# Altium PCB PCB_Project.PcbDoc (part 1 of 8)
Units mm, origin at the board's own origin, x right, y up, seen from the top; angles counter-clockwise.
Board outline 250 x 200 mm, 6 copper layers (Top Shielding/Sig, Sig 1, PWR, GND, Sig 4, Bottom Shielding/Sig), stack 1.568 mm thick; 736 components, 420 nets, 1929 pads, 2185 vias.
Unrouted connection lines stored in the file: 47.
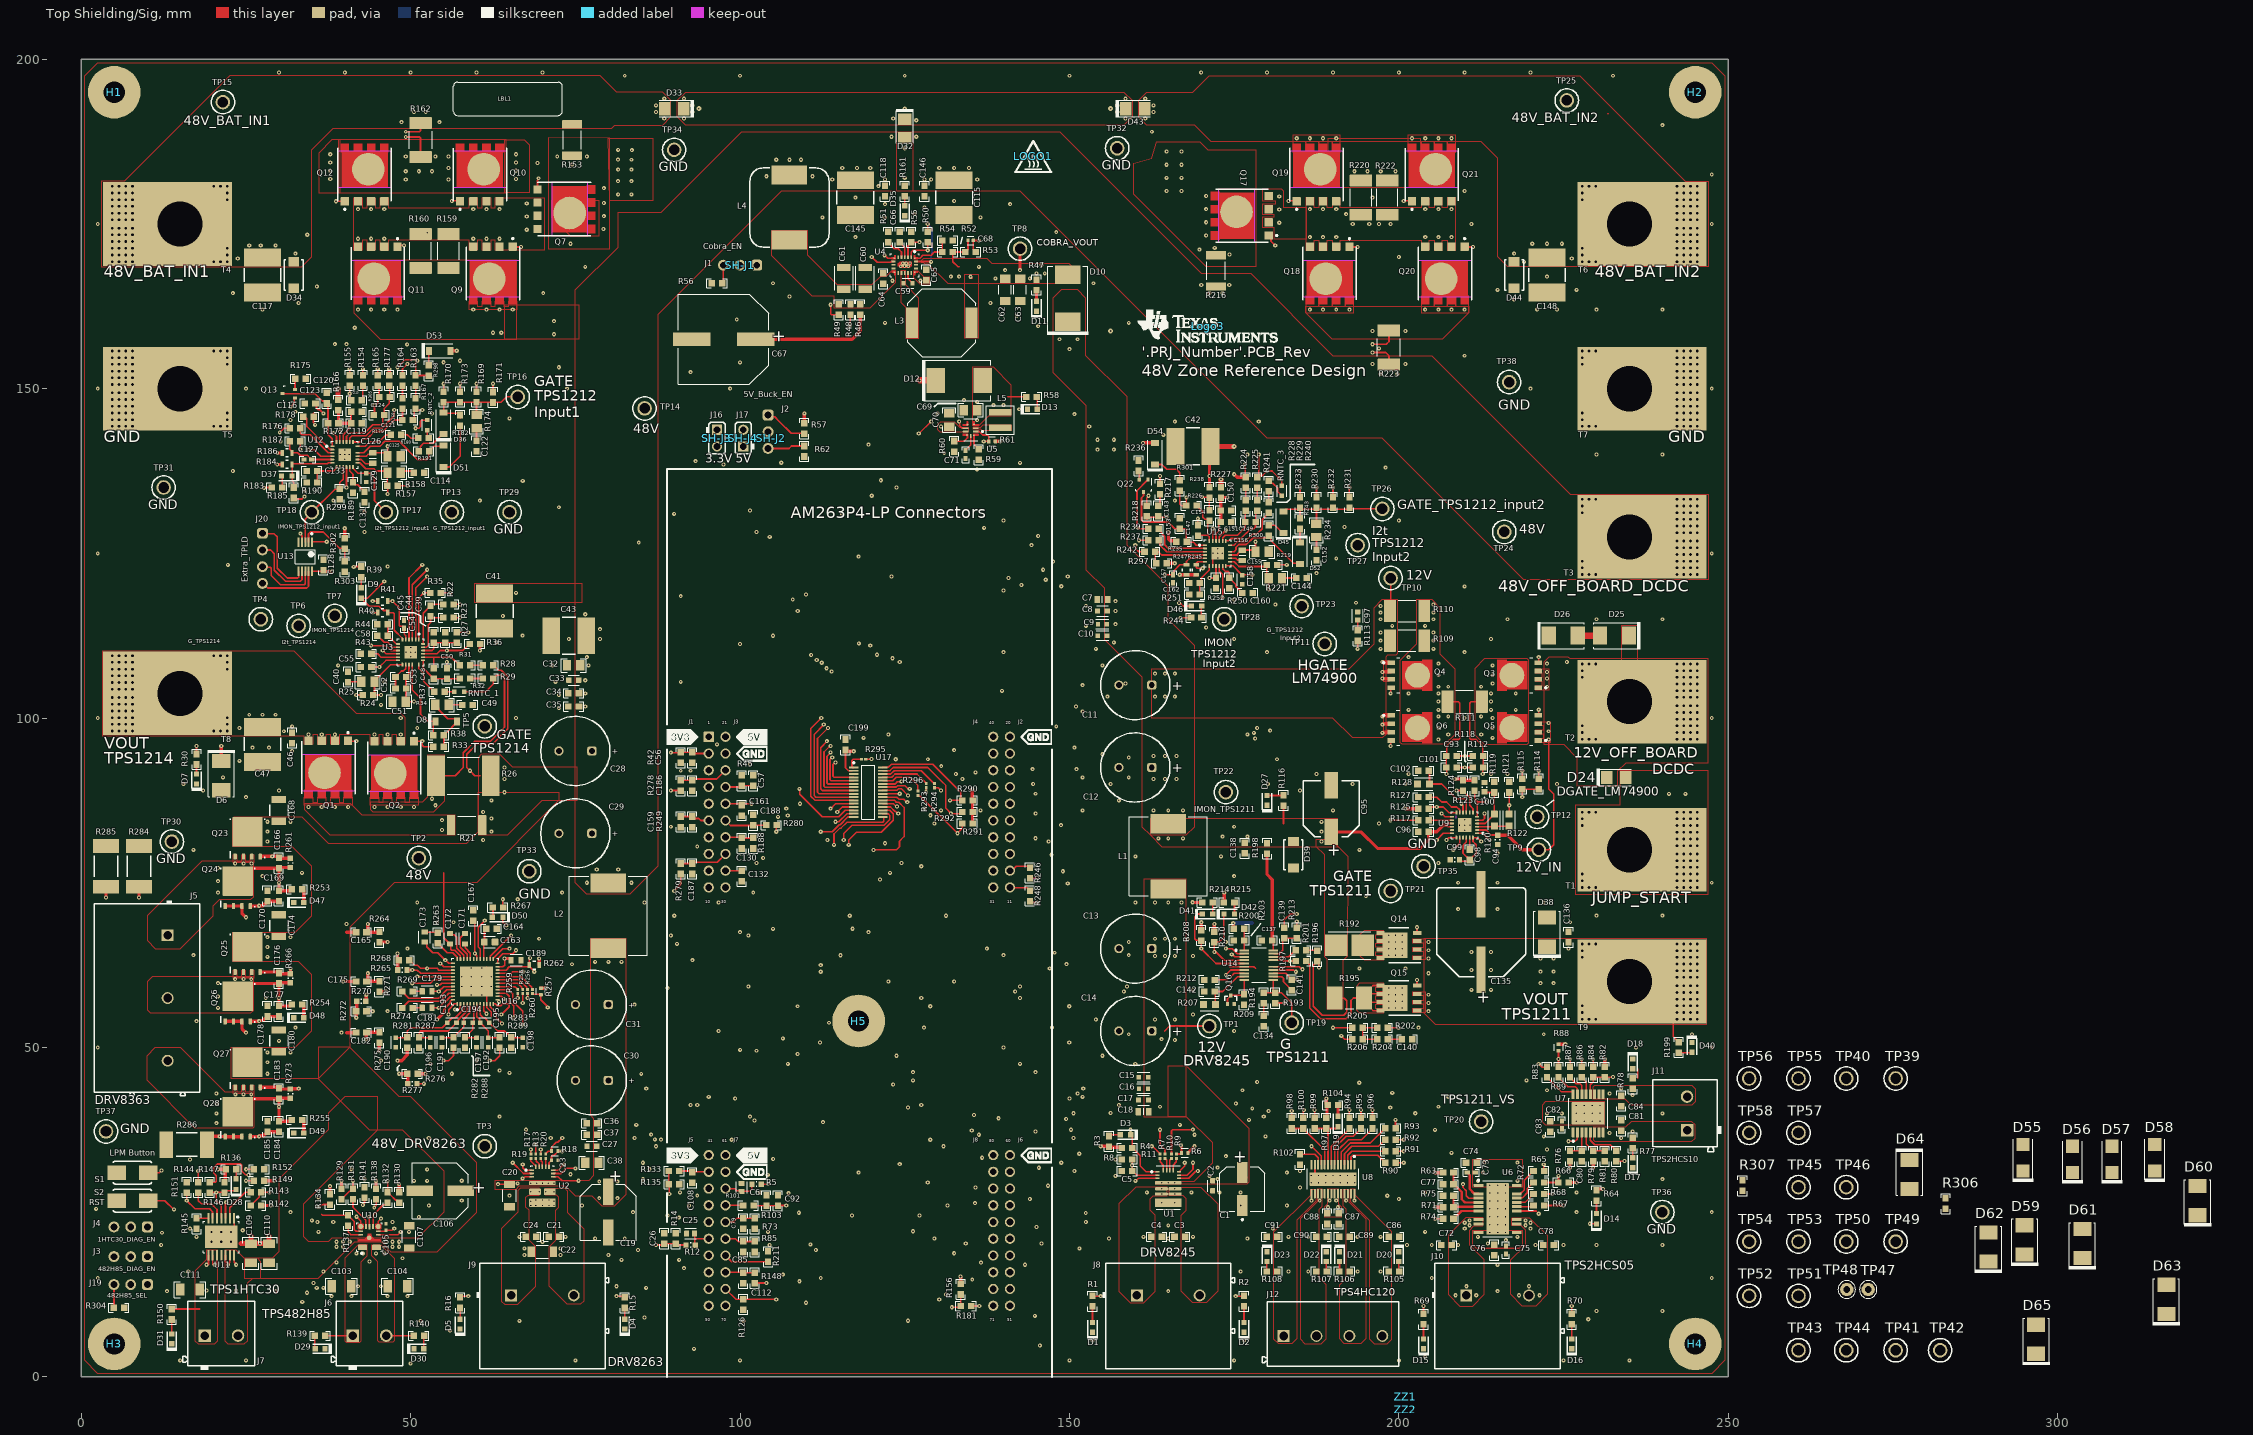
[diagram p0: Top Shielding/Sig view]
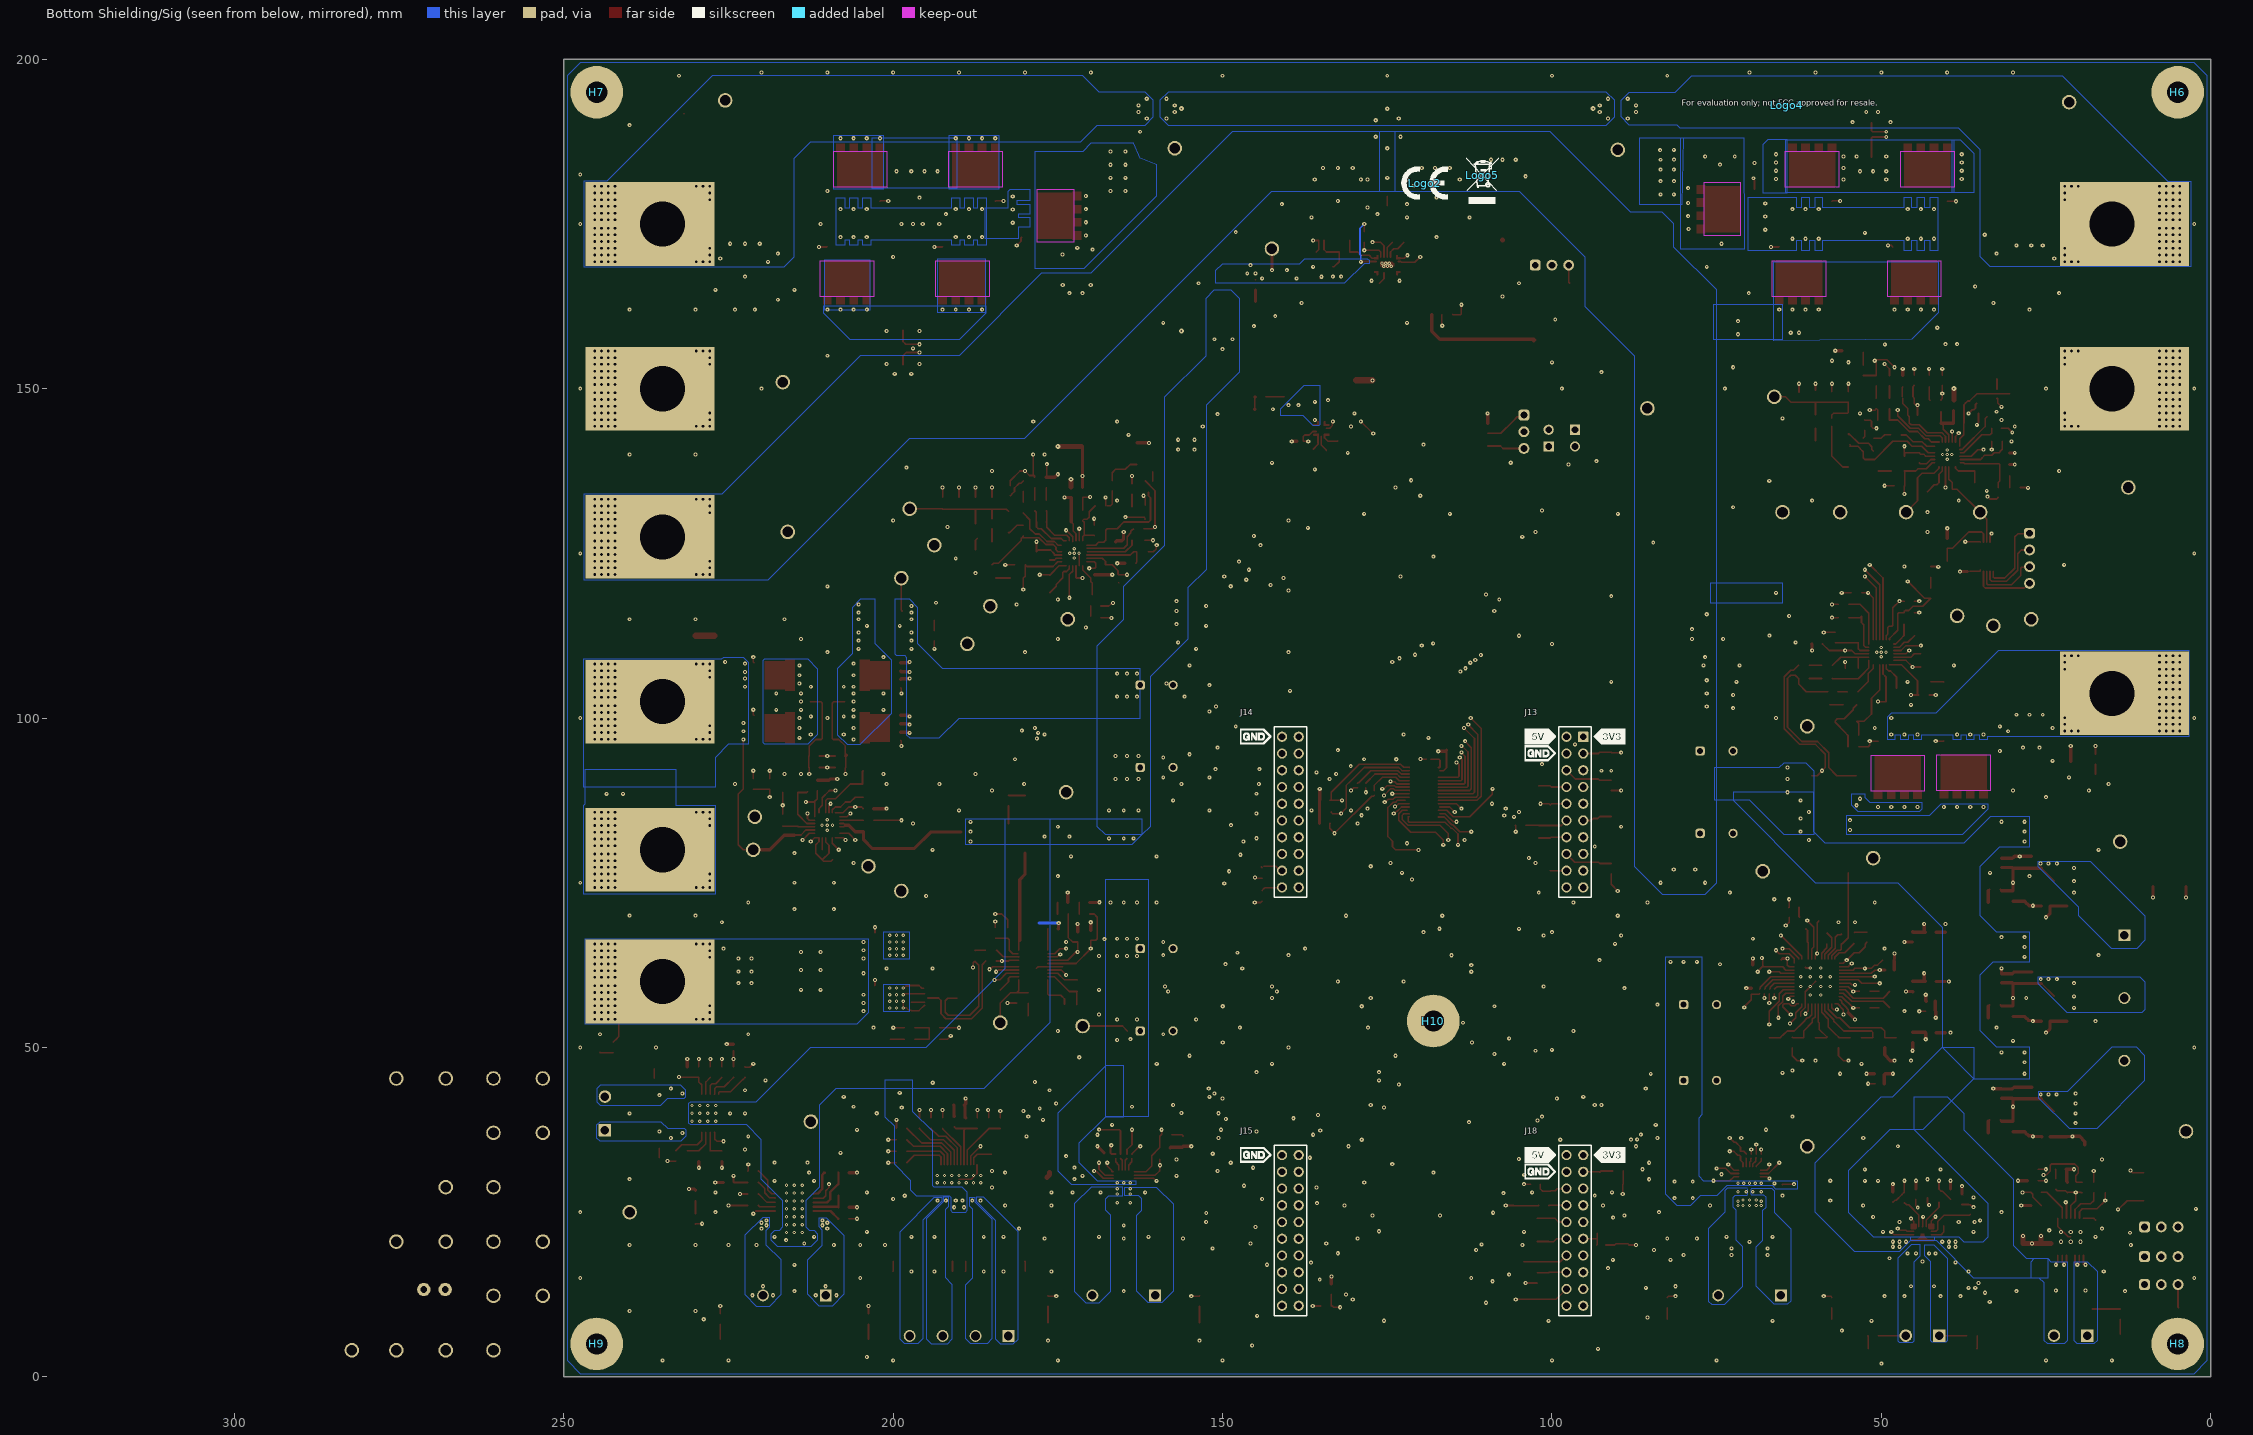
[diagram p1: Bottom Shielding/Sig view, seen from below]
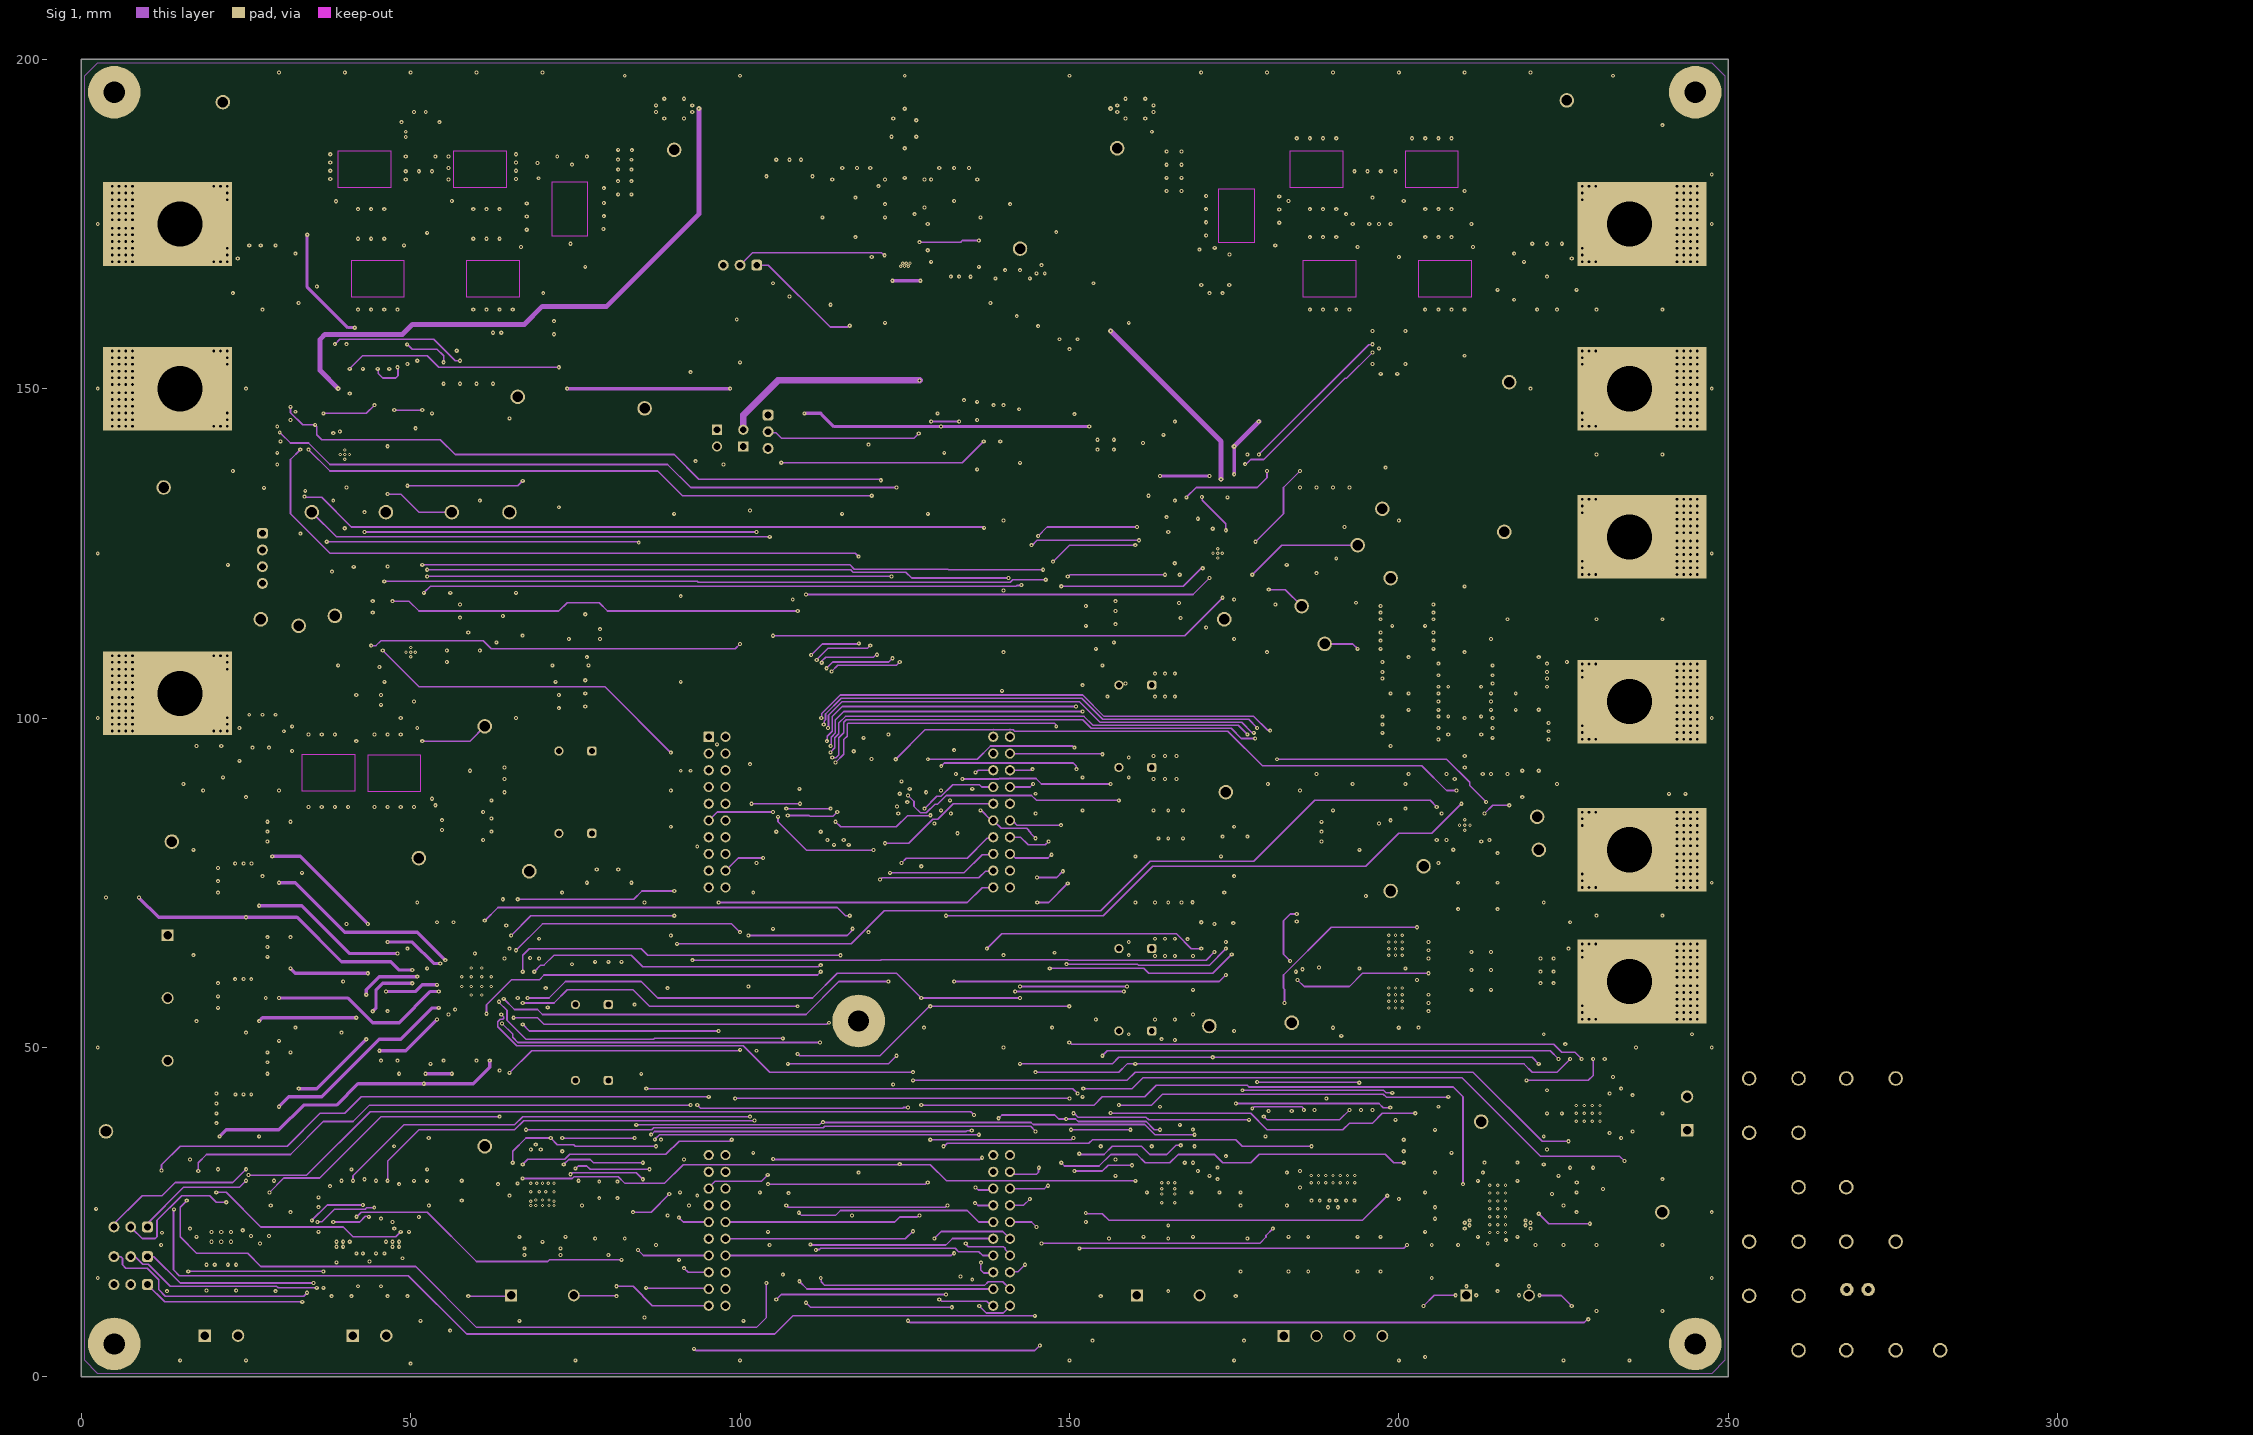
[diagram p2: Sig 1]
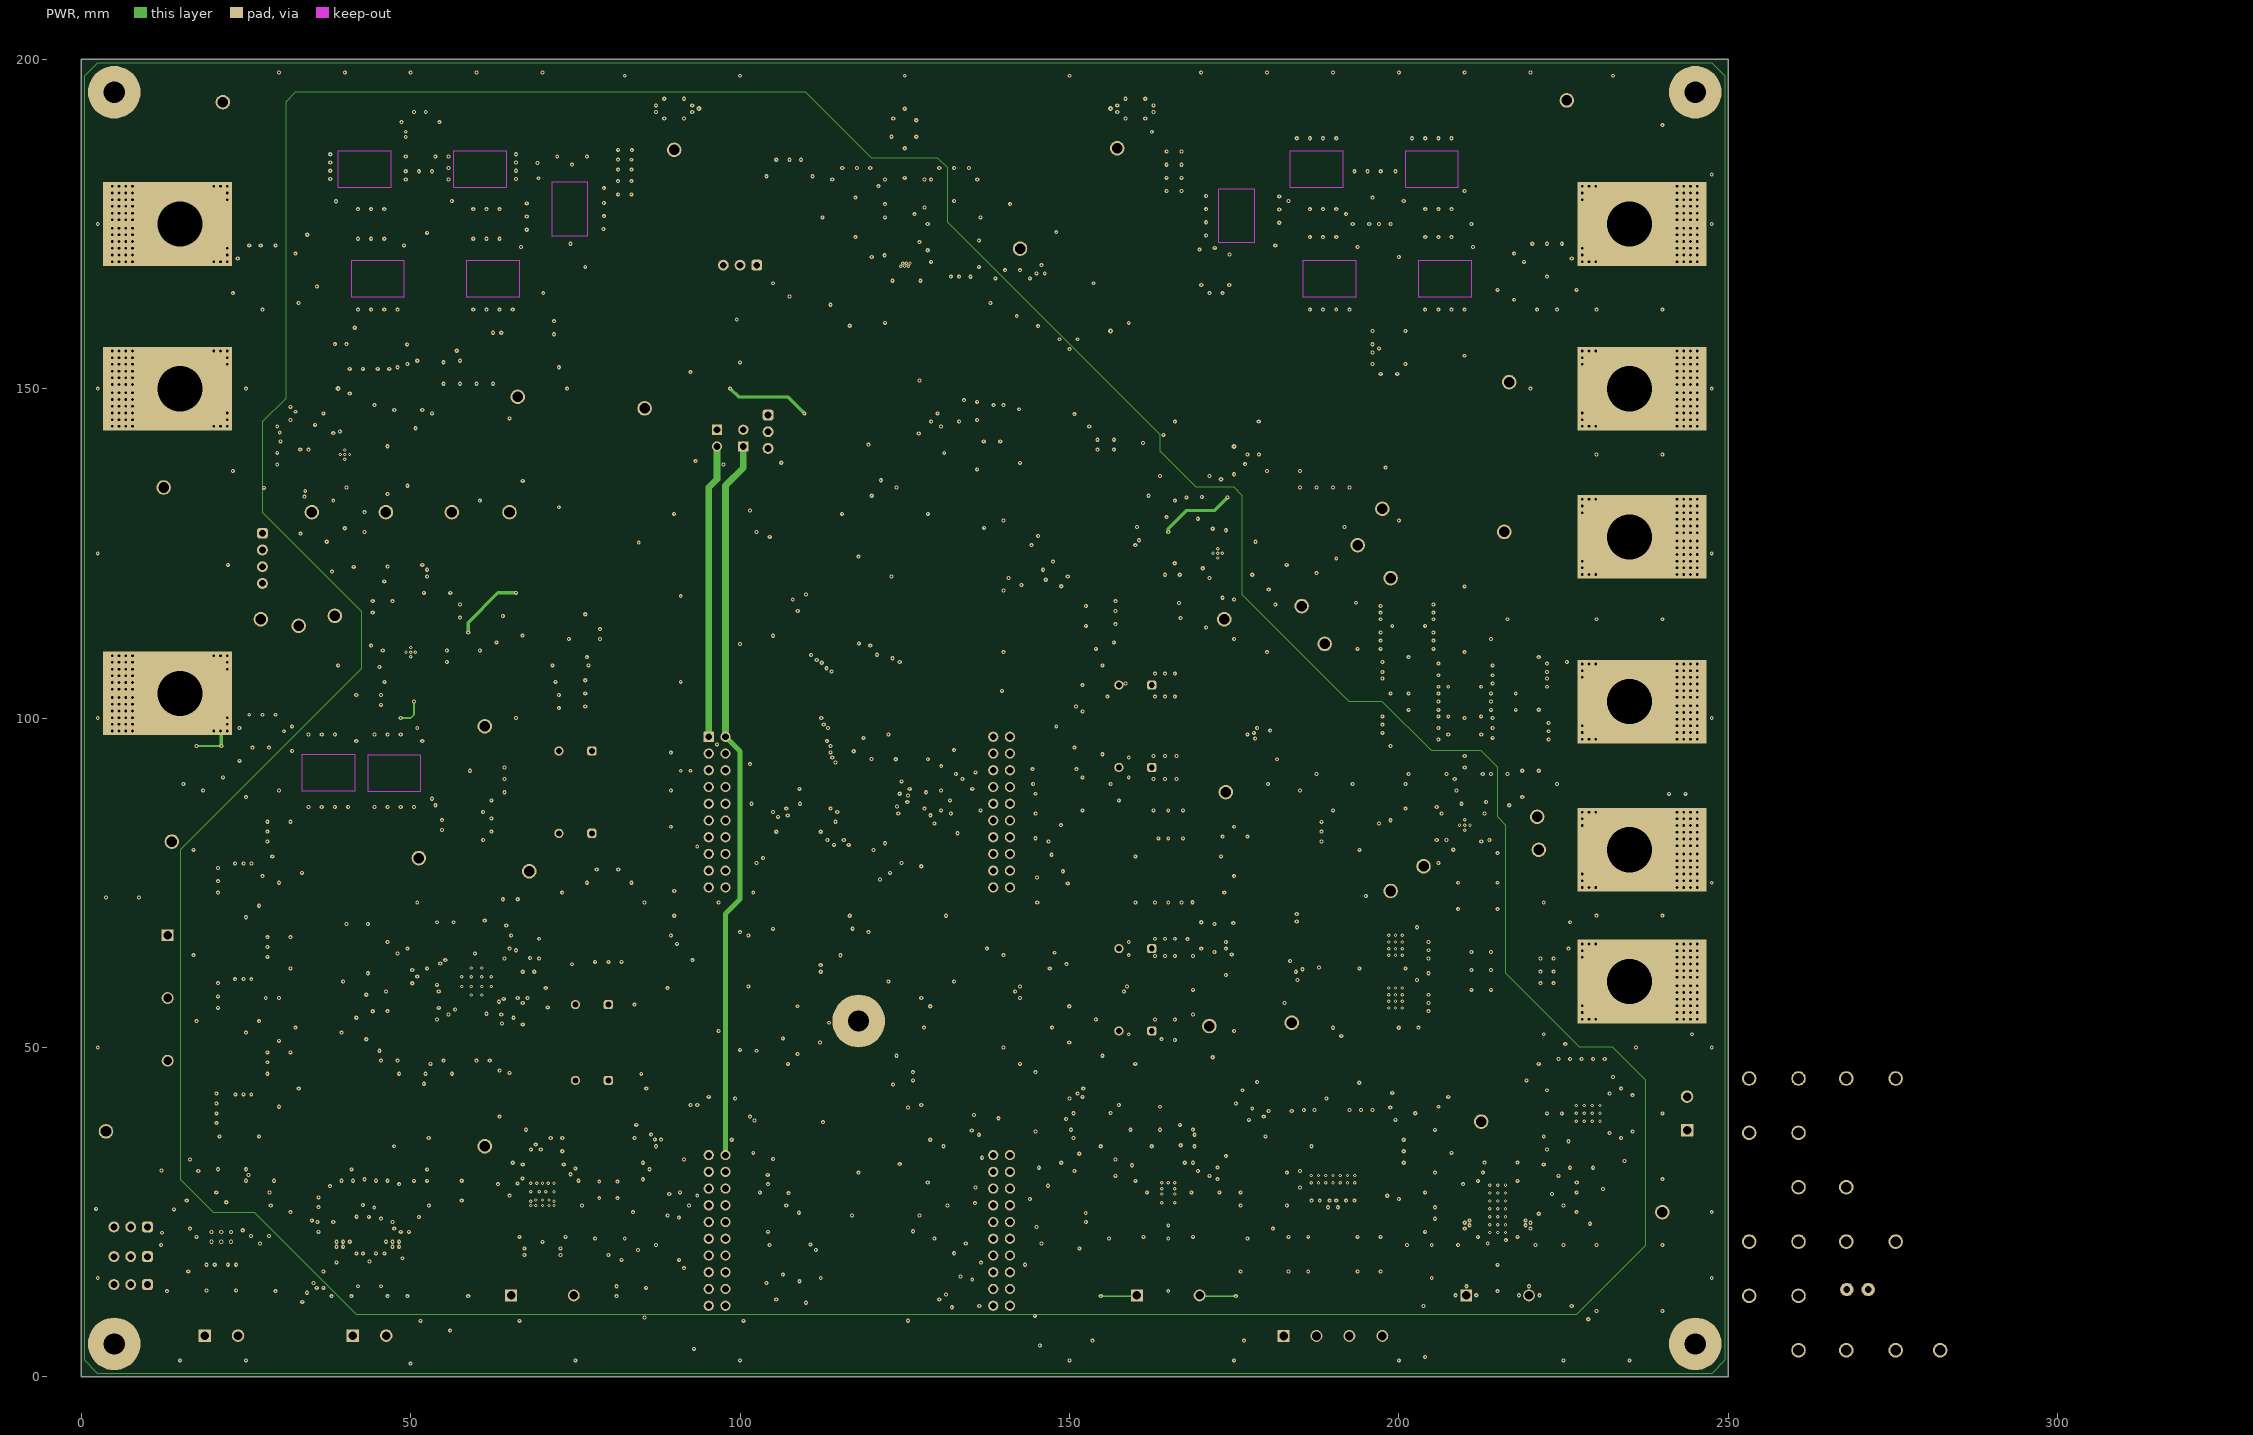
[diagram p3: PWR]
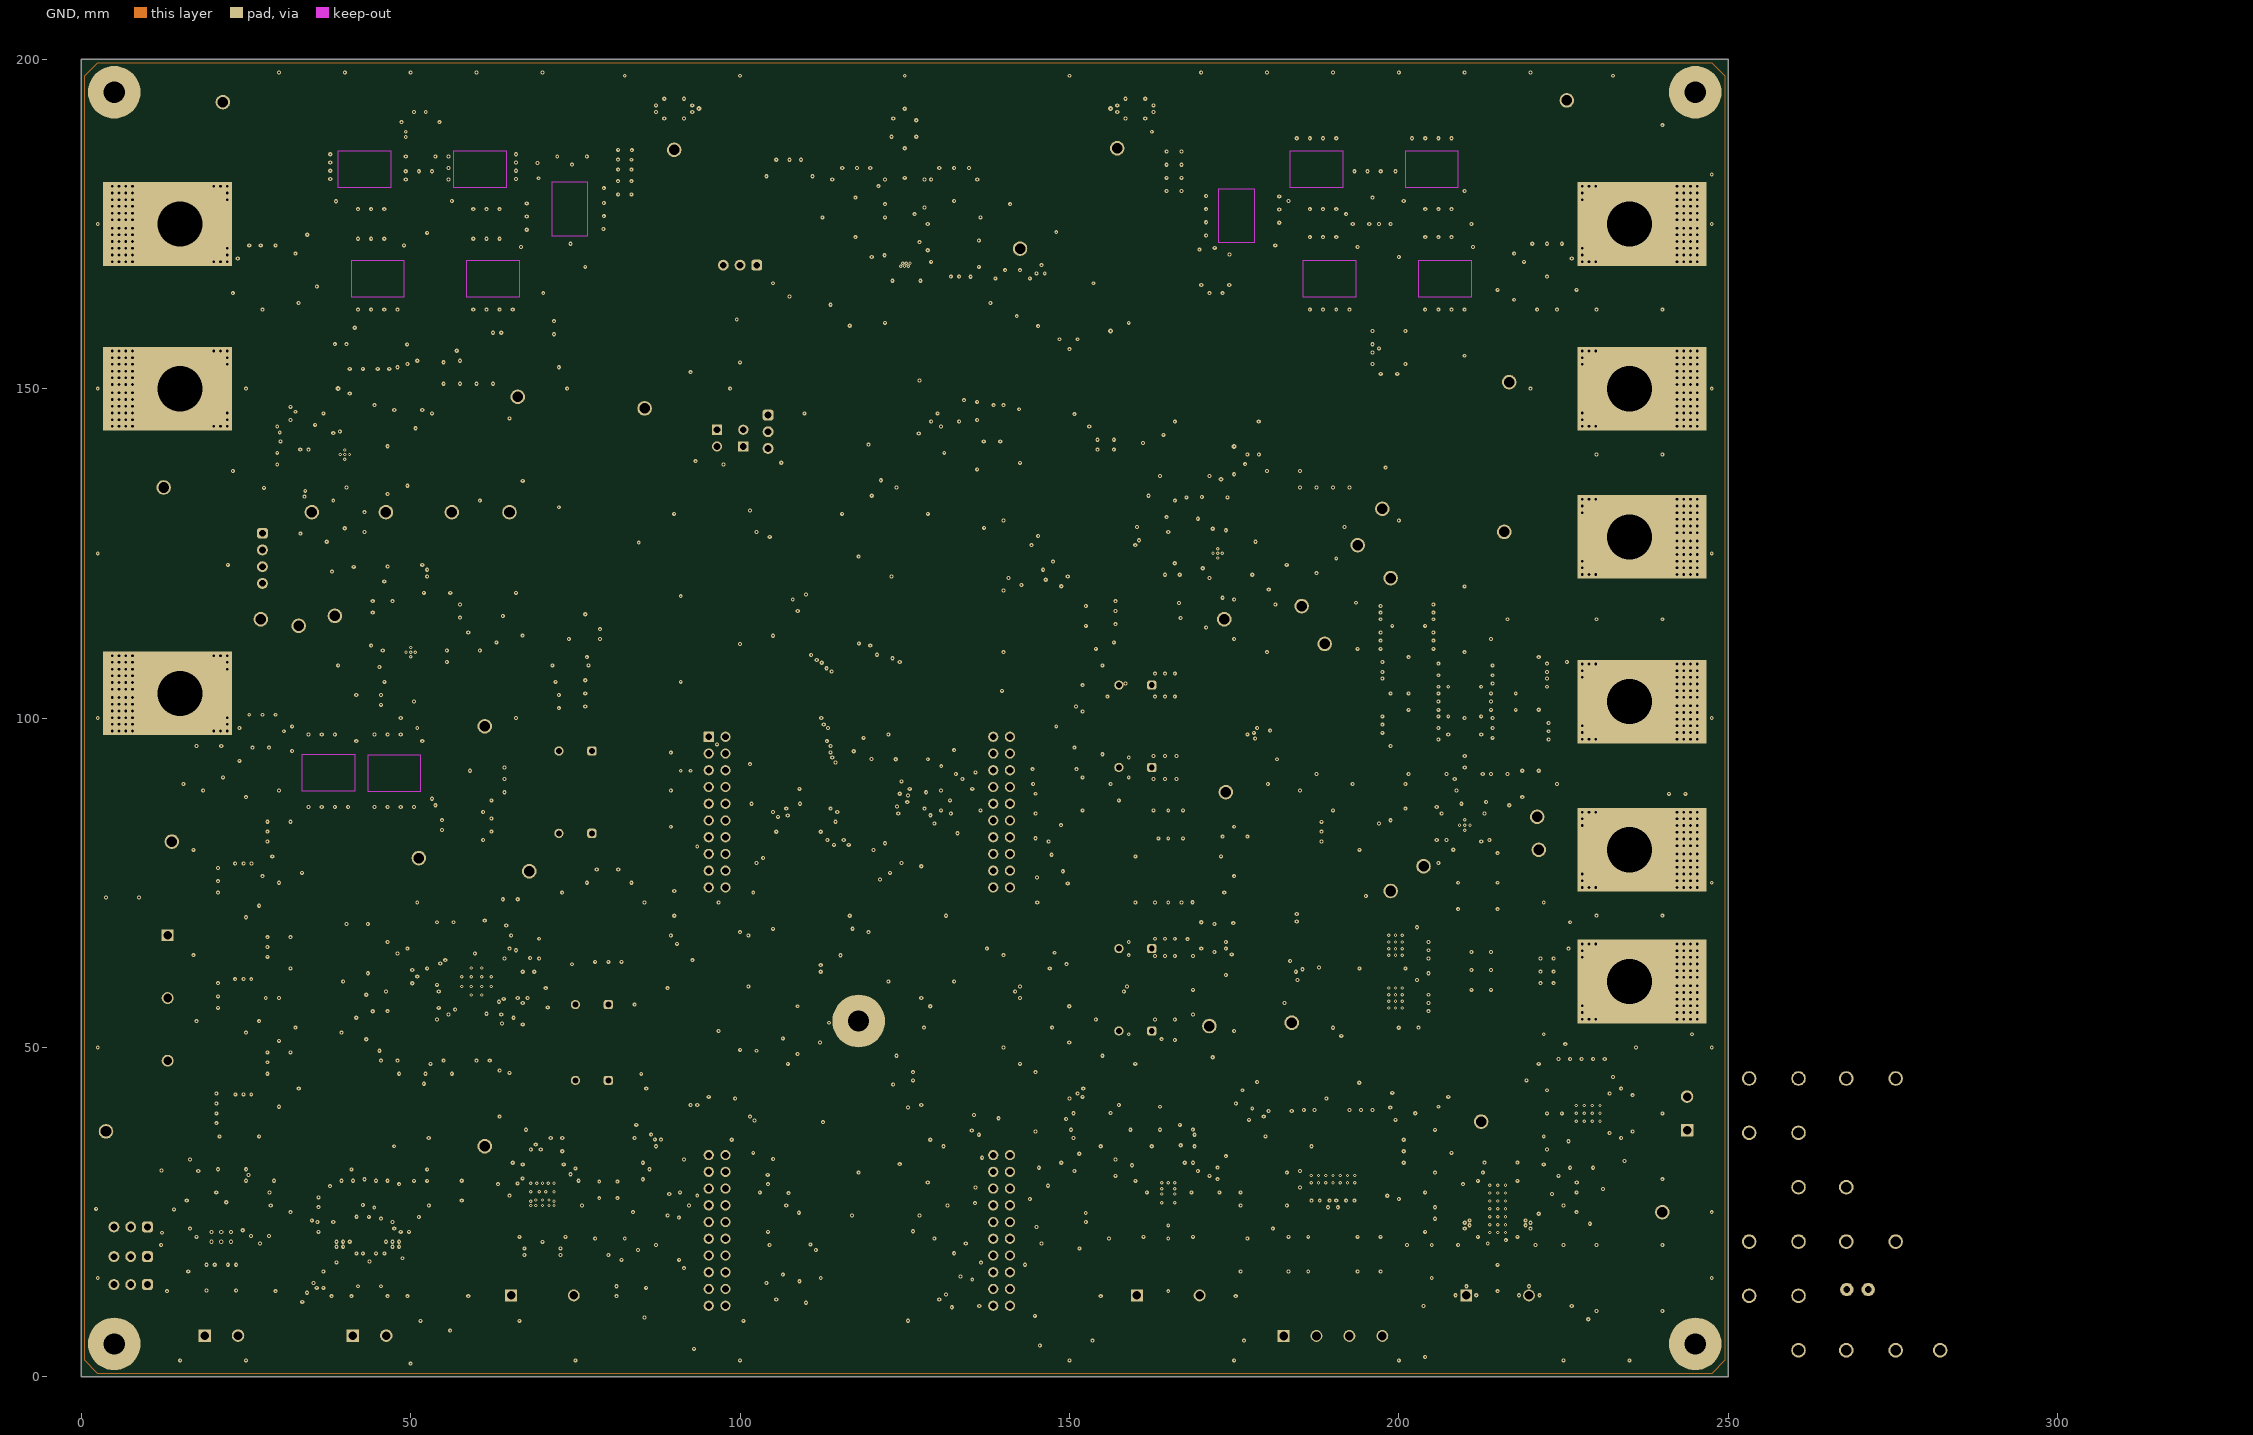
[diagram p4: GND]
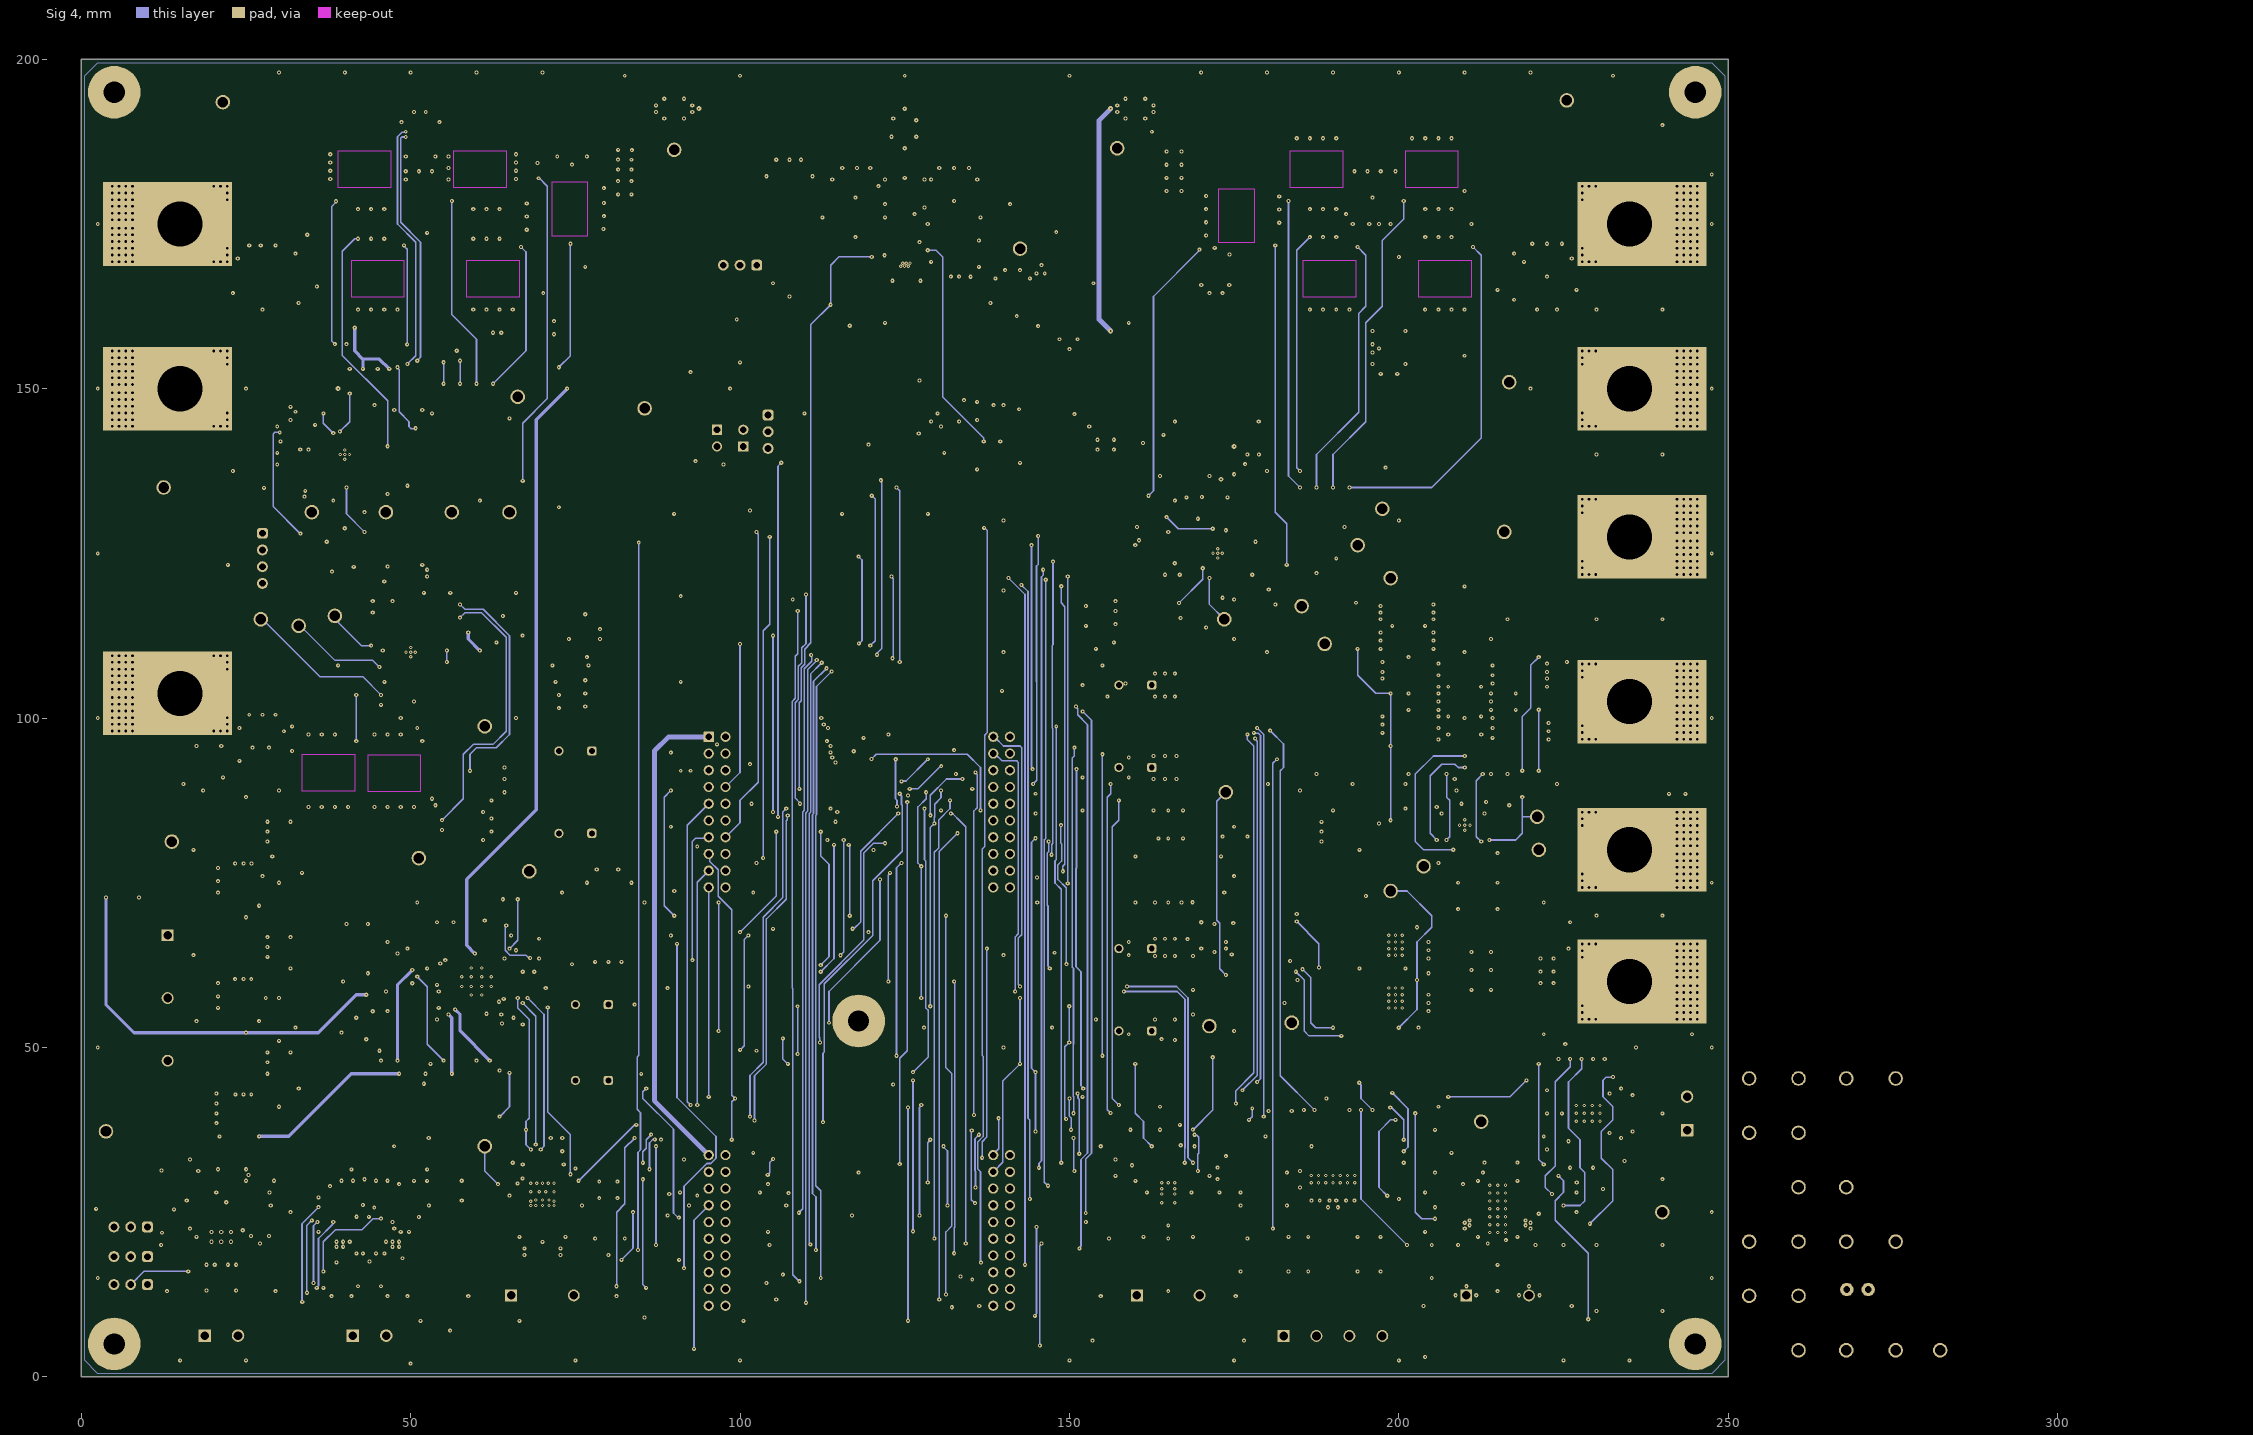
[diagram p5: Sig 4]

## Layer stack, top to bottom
Top Solder: solder mask 0.0102, Solder Resist, Dk 3.5
Top Shielding/Sig: signal copper 0.07
Dielectric 1: prepreg 0.0711, PP-006, Dk 4.1
Sig 1: signal copper 0.035
Dielectric 2: prepreg 0.0711, PP-006, Dk 4.1
PWR: signal copper 0.035
Dielectric 3: core 1.0033, FR-4 High Tg, Dk 4.8
GND: signal copper 0.035
Dielectric 4: prepreg 0.0711, PP-006, Dk 4.1
Sig 4: signal copper 0.035
Dielectric 5: prepreg 0.0711, PP-006, Dk 4.1
Bottom Shielding/Sig: signal copper 0.07
Bottom Solder: solder mask 0.0102, Solder Resist, Dk 3.5

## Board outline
0,0 0,200 250,200 250,0

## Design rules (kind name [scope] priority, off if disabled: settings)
AcuteAngle [All] p1: minimum=4.50000000000000E+0001 checktracksonly=FALSE
AssemblyTestPointUsage [All] p1: valid=2
BoardOutlineClearance BoardOutlineClearance_MountingHoles [OnCopper and InComponentClass('Mounting Holes')] p1: gap=1 ignorepadtopadclearanceinfootprint=FALSE
BoardOutlineClearance BoardOutlineClearance_Poly [OnCopper and IsPoly] p2: gap=0.5 ignorepadtopadclearanceinfootprint=FALSE
BoardOutlineClearance [OnCopper and Not InComponentClass('Logo') and not InComponentClass('FiducialMark') and not InRegion(1000,500,4000,800) and not InPoly] p3: gap=1.016 ignorepadtopadclearanceinfootprint=FALSE
Clearance Clearance_Keepouts [((IsTrack Or IsArc) And Not InPoly) And IsFree and IsKeepOut vs ((IsTrack Or IsArc) And Not InPoly) And IsFree and IsKeepOut] p1: gap=0 ignorepadtopadclearanceinfootprint=TRUE
Clearance Clearance_Poly [InPolygon] p2: gap=0.178 ignorepadtopadclearanceinfootprint=TRUE
Clearance Clearance_FiducialMark [IsKeepOut and InComponentClass('FiducialMark') vs IsPad and InComponentClass('FiducialMark')] p3: gap=0 ignorepadtopadclearanceinfootprint=TRUE
Clearance [All] p4: gap=0.2 ignorepadtopadclearanceinfootprint=TRUE
ComponentClearance ComponentClearance_MountingHoles_FiducialMarks [InComponentClass('Mounting Holes') vs InComponentClass('FiducialMark')] p1: gap=1.27 collisioncheckmode=3 verticalgap=0.254 showdistances=FALSE
ComponentClearance ComponentClearance_Shunt [InComponentClass('Header') vs InComponentClass('Shunt')] p2: gap=0 collisioncheckmode=3 verticalgap=0 showdistances=FALSE
ComponentClearance ComponentClearance_Logo [InComponentClass('Logo')] p3: gap=0.5 collisioncheckmode=3 verticalgap=0 showdistances=FALSE
ComponentClearance ComponentClearance_ScrewToNut [(HasFootprint('NY PMS 440 0025 PH')) vs (HasFootprint('Keystone_1902C'))] p4: gap=0.127 collisioncheckmode=3 verticalgap=0.254 showdistances=FALSE
ComponentClearance ComponentClearance_MountingHoles [InComponentClass('Mounting Holes') vs InComponentClass('Standoffs')] p5: gap=0 collisioncheckmode=3 verticalgap=0 showdistances=FALSE
ComponentClearance ComponentClearance_SmallPassives [HasFootprint('0201*') or HasFootprint('0402*') or HasFootprint('0508') or HasFootprint('0603*') or HasFootprint('0612') or HasFootprint('0805*') or HasFootprint('0815*') or HasFootprint('0830*') or HasFootprint('1206*') or HasFootprint('1210*') or HasFootprint('1808*') or HasFootprint('1812*') or HasFootprint('1825*') or HasFootprint('2010*') or HasFootprint('2220*') or HasFootprint('2225*') or HasFootprint('2512*') or HasFootprint('2728*') or HasFootprint('3518*') vs HasFootprint('0201*') or HasFootprint('0402*') or HasFootprint('0508') or HasFootprint('0603*') or HasFootprint('0612') or HasFootprint('0805*') or HasFootprint('0815*') or HasFootprint('0830*') or HasFootprint('1206*') or HasFootprint('1210*') or HasFootprint('1808*') or HasFootprint('1812*') or HasFootprint('1825*') or HasFootprint('2010*') or HasFootprint('2220*') or HasFootprint('2225*') or HasFootprint('2512*') or HasFootprint('2728*') or HasFootprint('3518*')] p6: gap=0.38 collisioncheckmode=3 verticalgap=0.254 showdistances=FALSE
ComponentClearance ComponentClearance_THtoSMT [IsThruComponent vs IsSMTComponent] p7: gap=0.762 collisioncheckmode=3 verticalgap=0.762 showdistances=FALSE
ComponentClearance ComponentClearance_THtoTH [IsThruComponent vs IsThruComponent] p8: gap=0.508 collisioncheckmode=3 verticalgap=0.762 showdistances=FALSE
ComponentClearance [All] p9: gap=0.508 collisioncheckmode=3 verticalgap=0.254 showdistances=FALSE
DiffPairsRouting [All] p1: maxlimit=2.54 minlimit=0.254 mostfreqgap=0.254 toplayer_minwidth=0.381 toplayer_maxwidth=0.381 toplayer_prefwidth=0.381 midlayer1_minwidth=0.381 midlayer1_maxwidth=0.381 midlayer1_prefwidth=0.381 midlayer2_minwidth=0.381 midlayer2_maxwidth=0.381 midlayer2_prefwidth=0.381 midlayer3_minwidth=0.381 midlayer3_maxwidth=0.381 midlayer3_prefwidth=0.381 midlayer4_minwidth=0.381 midlayer4_maxwidth=0.381 midlayer4_prefwidth=0.381 bottomlayer_minwidth=0.381 bottomlayer_maxwidth=0.381 bottomlayer_prefwidth=0.381 maxuncoupledlength=25.4
FabricationTestPointUsage TestPointUsage [All] p1: valid=2 allowmultiple=FALSE
FabricationTestpoint Testpoint [All] p1: side=3 testpointundercomponent=TRUE minsize=1.016 maxsize=2.54 preferedsize=1.524 minholesize=0 maxholesize=1.016 preferedholesize=0.813 testpointgrid=0.025 allowsidetop=TRUE allowsidebottom=TRUE usegrid=TRUE gridtolerance=0
FanoutControl Fanout_LCC [IsLCC] p1: bgadir=Out bgaviamode=Centered fanoutstyle=Auto fanoutdirection=Alternating viagrid=0.025 // Fanout_LCC (Default Rule)
FanoutControl Fanout_BGA [IsBGA] p2: bgadir=Out bgaviamode=Centered fanoutstyle=Auto fanoutdirection=Alternating viagrid=0.025 // Fanout_BGA (Default Rule)
FanoutControl Fanout_Default [All] p4: bgadir=Out bgaviamode=Centered fanoutstyle=Auto fanoutdirection=Alternating viagrid=0.025 // Fanout_Default (Default Rule)
FanoutControl Fanout_Small [(CompPinCount < 5)] p5: bgadir=Out bgaviamode=Centered fanoutstyle=Auto fanoutdirection=OutThenIn viagrid=0.025 // Fanout_Small (Default Rule)
HoleSize [All] p1: absolutevalues=TRUE maxlimit=7 minlimit=0.2 maxpercent=80.000 minpercent=20.000
MinimumAnnularRing MinimumAnnularRing_ThermalPadVias [IsVia and InAnyComponent] p1: minimumring=0.15
MinimumAnnularRing [All] p2: minimumring=0.15
MinimumSolderMaskSliver MinMaskSliver_RZT [HasFootprint('RZT0020A-MFG')] p1: minsoldermaskwidth=0.025
MinimumSolderMaskSliver MinimumSolderMaskSliver_Logo [InComponentClass('Logo') vs InComponentClass('Logo')] p2: minsoldermaskwidth=0.018
MinimumSolderMaskSliver [All] p3: minsoldermaskwidth=0.1
NetAntennae NetAntennae_PwrLugs [InComponentClass('PowerLug') and InNet('GND')] p1: netantennaetolerance=0
NetAntennae [All] p2: netantennaetolerance=0
PlaneConnect [All] p1: planeconnectstyle=Direct reliefexpansion=0.254 reliefentries=4 reliefconductorwidth=0.254 reliefairgap=0.254
PolygonConnect "GND Thermals 2mm" [InNet('GND') vs InComponentClass('PowerLug')] p1: connectstyle=Direct reliefconductorwidth=2 reliefentries=4 polygonreliefangle="90 Angle" airgapwidth=0.35
PolygonConnect "GND Thermals 0.5mm" [InNet('GND') vs HasFootprint('KCM*') or HasFootprint('*1210*') or HasFootprint('SM_RADIAL*') or HasFootprint('SMB') or HasFootprint('SMC') or HasFootprint('*DO-214*') or HasFootprint('*SMT_800*') or HasFootprint('AFK_1250*') or HasFootprint('FP-EEE*') or HasFootprint('FP-EMH*')] p2: connectstyle=Direct reliefconductorwidth=0.5 reliefentries=4 polygonreliefangle="90 Angle" airgapwidth=0.25
PolygonConnect "GND Thermals 0.25mm" [InNet('GND') vs InComponentClass('GND Thermals 0.25mm') or HasFootprint('*0402*') or HasFootprint('*0603*')  or HasFootprint('*0805*')  or HasFootprint('*1206*') or HasFootprint('LTST*') or HasFootprint('SW_1478*') or HasFootprint('SOD-123*')   or HasFootprint('WCAP*') or HasFootprint('SMA*') or InComponentClass('Header') or InComponentClass('GND-TP')] p3: connectstyle=Direct reliefconductorwidth=0.25 reliefentries=4 polygonreliefangle="90 Angle" airgapwidth=0.25
PolygonConnect "Full Pour" [All] p4: connectstyle=Direct reliefconductorwidth=0.254 reliefentries=4 polygonreliefangle="90 Angle" airgapwidth=0.254
RoutingVias ThermalPadVias [IsVia and InAnyComponent] p1: holewidth=0.2 width=0.5 viastyle="Through Hole" minholewidth=0.127 minwidth=0.5 maxholewidth=0.432 maxwidth=0.838
RoutingVias [All] p2: holewidth=0.406 width=0.864 viastyle="Through Hole" minholewidth=0.127 minwidth=0.584 maxholewidth=1.016 maxwidth=1.651
SilkToBoardRegionClearance [Not ((IsComment or IsDesignator) And (Hide <> 'False')) and not InRegion(1000,500,4000,800)] p1:
SilkToSilkClearance SilkToSilkClearance_Pb-FreeLogo [(HasFootprint('Pb-Free_Overlay_Medium') OR HasFootprint('Pb-Free_Overlay_Small')) vs (HasFootprint('Pb-Free_Overlay_Medium') OR HasFootprint('Pb-Free_Overlay_Small'))] p1: silktosilkclearance=0
SilkToSilkClearance [All] p2: silktosilkclearance=0.1
SilkToSolderMaskClearance SilkToSolderMaskClearance_RZT [IsPad vs HasFootprint('RZT0020A-MFG')] p1: minsilkscreentomaskgap=0.1 clearancetoexposedcopper=FALSE
SilkToSolderMaskClearance SilkToMaskClearance_LibErrors [IsPad vs HasFootprint('LTST*') or HasFootprint('0402*') or HasFootprint('0603*') or HasFootprint('0805*') or HasFootprint('SMA*') or HasFootprint('SMB*') or HasFootprint('SOD*') or HasFootprint('SMC')] p2: minsilkscreentomaskgap=0.01 clearancetoexposedcopper=FALSE
SilkToSolderMaskClearance SilkToComponentPadClearance [(IsPad or IsFill or IsRegion) and InAnycomponent vs HasFootprint('LTST*')] p3: minsilkscreentomaskgap=0.1 clearancetoexposedcopper=TRUE
SilkToSolderMaskClearance "Silk to Solder Mask Opening" [All] p4: minsilkscreentomaskgap=0.1 clearancetoexposedcopper=FALSE
SolderMaskExpansion [All] p1: expansion=0.05 istentingtop=FALSE
UnRoutedNet [All] p1: checkbadconnections=TRUE
Width [All] p1: maxlimit=2.54 minlimit=0.125 preferedwidth=0.25 checkconnectedcopper=TRUE
13 further rules are at their usual default settings.

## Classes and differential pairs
component class Shunt: SH-J1 SH-J2 SH-J3 SH-J4
component class GND-TP: TP29 TP30 TP31 TP32 TP33 TP34 TP35 TP36 TP37 TP38
component class Standoffs: H6 H7 H8 H9 H10
component class "U_(SPI Expander) TXE8124-Q1": C199 R290 R291 R292 R293 R294 R295 R296 U17
component class "U_(BLDC) DRV8363-Q1": C163 C164 C165 C166 C167 C168 C169 C170 C171 C172 C173 C174 C175 C176 C177 C178 C179 C180 C181 C182 C183 C184 C185 C186 C187 C188 C189 C190 C191 C192 C193 C194 C195 C196 C197 C198 D47 D48 D49 D50 Q23 Q24 Q25 Q26 Q27 Q28 R253 R254 R255 R256 R257 R258 R259 R260 R261 R262 R263 R264 R265 R266 R267 R268 R269 R270 R271 R272 R273 R274 R275 R276 R277 R278 R279 R280 R281 R282 R283 R284 R285 R286 R287 R288 R289 U16
component class "U_AM26 Connectors": J13 J14 J15 J16 J17 J18 S1 S2
component class U_TPS1214-Q1: C39 C40 C41 C42 C43 C44 C45 C46 C47 C48 C49 C50 C51 C52 C53 C54 C55 C56 C57 C58 D6 D7 D8 D9 Q1 Q2 R21 R22 R23 R24 R25 R26 R27 R28 R29 R30 R31 R32 R33 R34 R35 R36 R37 R38 R39 R40 R41 R42 R43 R44 R45 RNTC_1 TP4 TP5 TP6 TP7 TP39 TP40 TP55 TP56 U3
component class U_TPS1211-Q1: C134 C135 C136 C137 C138 C139 C140 C141 C142 D38 D39 D40 D41 D42 Q14 Q15 Q16 R192 R193 R194 R195 R196 R197 R198 R199 R200 R201 R202 R203 R204 R205 R206 R207 R208 R209 R210 R211 R212 R213 R214 R215 TP19 TP20 TP21 TP22 TP57 TP58 U14
component class U_TPS4HC120-Q1: C86 C87 C88 C89 C90 C91 C92 D19 D20 D21 D22 D23 D55 D56 D57 D58 R90 R91 R92 R93 R94 R95 R96 R97 R98 R99 R100 R101 R102 R103 R104 R105 R106 R107 R108 R307 TP45 TP46 U8
component class "U_Motor Drivers": C1 C2 C3 C4 C5 C6 C7 C8 C9 C10 C11 C12 C13 C14 C15 C16 C17 C18 C19 C20 C21 C22 C23 C24 C25 C26 C27 C28 C29 C30 C31 C32 C33 C34 C35 C36 C37 C38 D1 D2 D3 D4 D5 L1 L2 R1 R2 R3 R4 R5 R6 R7 R8 R9 R10 R11 R12 R13 R14 R15 R16 R17 R18 R19 R20 TP1 TP2 TP3 U1 U2
component class U_LM74900-Q1: 12V_OFF_BOARD_DCDC C93 C94 C95 C96 C97 C98 C99 C100 C101 C102 D24 D25 D26 D27 JUMP_START Q3 Q4 Q5 Q6 R109 R110 R111 R112 R113 R114 R115 R116 R117 R118 R119 R120 R121 R122 R123 R124 R125 R126 R127 R128 T1 T2 TP9 TP10 TP11 TP12 U9
component class U_Power: C59 C60 C61 C62 C63 C64 C65 C66 C67 C68 C69 C70 C71 D10 D11 D12 D13 J1 J2 L3 L4 L5 R46 R47 R48 R49 R50 R51 R52 R53 R54 R55 R56 R57 R58 R59 R60 R61 R62 TP8 U4 U5
component class U_Backbone_input2: 48V_IN C143 C144 C145 C146 C147 C148 C149 C150 C151 C152 C153 C154 C155 C156 C157 C158 C159 C160 C161 C162 D43 D44 D45 D46 D52 D54 GND Q17 Q18 Q19 Q20 Q21 Q22 R216 R217 R218 R219 R220 R221 R222 R223 R224 R225 R226 R227 R228 R229 R230 R231 R232 R233 R234 R235 R236 R237 R238 R239 R240 R241 R242 R243 R244 R245 R246 R247 R248 R249 R250 R251 R252 R297 R300 R301 RNTC_3 T6 T7 TP23 TP24 TP25 TP26 TP27 TP28 TP49 TP50 TP53 TP54 U15
component class U_Backbone_input1: 48V_IN 48V_OFF_BOARD_DCDC C113 C114 C115 C116 C117 C118 C119 C120 C121 C122 C123 C124 C125 C126 C127 C128 C129 C130 C131 C132 C133 D32 D33 D34 D35 D36 D37 D51 D53 GND J20 Q7 Q9 Q10 Q11 Q12 Q13 R153 R154 R155 R156 R157 R158 R159 R160 R161 R162 R163 R164 R165 R166 R167 R168 R169 R170 R171 R172 R173 R174 R175 R176 R177 R178 R179 R180 R181 R182 R183 R184 R185 R186 R187 R188 R189 R190 R191 R298 R299 R302 R303 R305 RNTC_2 T3 T4 T5 TP13 TP14 TP15 TP16 TP17 TP18 TP47 TP48 TP51 TP52 U12 U13
component class "U_48V E-Fuse": C103 C104 C105 C106 C107 C108 C109 C110 C111 C112 D28 D29 D30 D31 D59 D60 D61 J3 J4 J19 R129 R130 R131 R132 R133 R134 R135 R136 R137 R138 R139 R140 R141 R142 R143 R144 R145 R146 R147 R148 R149 R150 R151 R152 R304 U10 U11
component class "U_12V E-Fuse": C72 C73 C74 C75 C76 C77 C78 C79 C80 C81 C82 C83 C84 C85 D14 D15 D16 D17 D18 D62 D63 D64 D65 R63 R64 R65 R66 R67 R68 R69 R70 R71 R72 R73 R74 R75 R76 R77 R78 R79 R80 R81 R82 R83 R84 R85 R86 R87 R88 R89 R306 TP41 TP42 TP43 TP44 U6 U7
component class "Top Sheet": GND J5 J6 J7 J8 J9 J10 J11 J12 T8 T9 TP29 TP30 TP31 TP32 TP33 TP34 TP35 TP36 TP37 TP38 TPS1211_OUT TPS1214_OUT
component class Header: J1 J2 J3 J4 J13 J14 J15 J16 J17 J18 J19 J20
component class "Mounting Holes": H1 H2 H3 H4 H5
component class Logo: Logo3
component class U_PCB_Project_Hardware: H1 H2 H3 H4 H5 H6 H7 H8 H9 H10 LBL1 LOGO1 Logo2 Logo3 Logo4 Logo5 SH-J1 SH-J2 SH-J3 SH-J4 ZZ1 ZZ2 ZZ3 ZZ4
component class AssemblyNote: ZZ1 ZZ2 ZZ3 ZZ4
component class Label: LBL1

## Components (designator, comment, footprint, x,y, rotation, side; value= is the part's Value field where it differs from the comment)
C1 "EEE-HA1H100P" FP-EEE-HA1H100P_RADIAL-MFG 176.25,28.5 r90 top value=10µF
C2 "06035C104J4Z2A" FP-06035C104J4Z2A_0603-MFG 171.75,29 r90 top value=100nF
C3 "885012206095" 0603 166.75,21.25 r0 top value=0.1uF
C4 "885012206095" 0603 163.25,21.25 r180 top value=0.1uF
C5 "885012206095" 0603 158.75,31.25 r0 top value=0.1uF
C6 "C0603C104J5RAC7867" FP-C0603C104J5RAC7867_0603-MFG 100.25,28.75 r90 top value=100nF
C7 "CL10B105KB9VPJC" FP-CL10B105KB9VPJC_0603-MFG 155,118 r0 top value=1µF
C8 "06035C104J4Z2A" FP-06035C104J4Z2A_0603-MFG 155,116.25 r0 top value=100nF
C9 "GCE188R71H103KA01D" FP-GCE188R71H103KA01D_0603-MFG 155,114.25 r0 top value=10nF
C10 "CGA3E2X7R1H102K080AA" FP-CGA3E2X7R1H102K080AA_0603-MFG 155,112.5 r0 top value=1nF
C11 "860040875004" WCAP-ATUL_D10H20 160,105 r0 top
C12 "860040875004" WCAP-ATUL_D10H20 160,92.5 r0 top locked
C13 "860040875004" WCAP-ATUL_D10H20 160,65 r0 top locked
C14 "860040875004" WCAP-ATUL_D10H20 160,52.5 r0 top
C15 "CGA3E2X7R1H102K080AA" FP-CGA3E2X7R1H102K080AA_0603-MFG 161.25,45.5 r0 top value=1nF
C16 "GCE188R71H103KA01D" FP-GCE188R71H103KA01D_0603-MFG 161.25,43.75 r0 top value=10nF
C17 "06035C104J4Z2A" FP-06035C104J4Z2A_0603-MFG 161.25,42 r0 top value=100nF
C18 "CL10B105KB9VPJC" FP-CL10B105KB9VPJC_0603-MFG 161.25,40.25 r0 top value=1µF
C19 "EEE-2AA100UP" SM_RADIAL_E 80,25 r270 top value=10uF
C20 "C3216X7R2A104K160AA" 1206_180 65,27.5 r270 top value=0.1uF
C21 "CGA3E2X7R2A102K080AA" 0603 71.75,21.25 r0 top value=1000pF
C22 "C3216X7R2A104K160AA" 1206_180 70,19 r180 top value=0.1uF
C23 "885012105001" WCAP-CSGP_0402_L1W0.5H0.5 71.875,32.875 r0 top
C24 "CGA3E2X7R2A102K080AA" 0603 68.25,21.25 r180 top value=1000pF
C25 "C0603C104J5RAC7867" FP-C0603C104J5RAC7867_0603-MFG 92.5,21.75 r180 top value=100nF
C26 "885012206095" 0603 88.5,21 r270 top value=0.1uF
C27 "885012206120" FP-885012206120_0603-MFG 77.5,35 r0 top value=100nF
C28 "860040875004" WCAP-ATUL_D10H20 75,95 r0 top
C29 "860040875004" WCAP-ATUL_D10H20 75,82.5 r0 top
C30 "860040875004" WCAP-ATUL_D10H20 77.5,45 r0 top
C31 "860040875004" WCAP-ATUL_D10H20 77.5,56.5 r0 top
C32 "C2012X7S2A105K125AB" 0805_HV 74.75,108 r0 top value=1uF
C33 "885012206120" FP-885012206120_0603-MFG 74.75,105.75 r0 top value=100nF
C34 "885012206114" 0603 74.75,103.75 r0 top value=0.01uF
C35 "06031C102KAT2A" 0603 74.75,101.75 r180 top value=1000pF
C36 "06031C102KAT2A" 0603 77.5,38.5 r180 top value=1000pF
C37 "885012206114" 0603 77.5,36.75 r0 top value=0.01uF
C38 "C2012X7S2A105K125AB" 0805_HV 77.5,32.5 r0 top value=1uF
C39 "C0603X102K5RACTU" 0603 53,116.25 r90 top value=1000pF
C40 "CGA3E2X7R2A222K080AA" 0603 40.5,106.25 r270 top value=2200pF
C41 "KCM55WR72A156MH01K" KCM55W 62.75,116.25 r270 top value=15uF
C42 "KCM55WR72A156MH01K" KCM55W 168.75,141.25 r180 top value=15uF
C43 "KCM55WR72A156MH01K" KCM55W 74,112.5 r180 top value=15uF
C44 "HMK107B7104KAHT" 0603 55.25,112.25 r90 top value=0.1uF
C45 "CGA3E2X7R2A103K080AA" 0603 53.5,112.25 r90 top value=0.01uF
C46 "HMK107B7104KAHT" 0603 32,97 r270 top value=0.1uF
C47 "KCM55WR72A156MH01K" KCM55W 27.5,96 r270 top value=15uF
C48 "C0603X102K5RACTU" 0603 53.5,106.75 r90 top value=1000pF
C49 "RC0603FR-07200RL" 0603 58.625,102 r180 top value=0.22uF
C50 "C0603X102K5RACTU" 0603 55.5,106.75 r90 top value=1000pF
C51 "CGA4J2X7R2A104K125AA" 0805_HV 48.25,102.5 r180 top value=0.1uF
C52 "CGA3E2X7R1H473K080AA" 0603 48.5,104.5 r180 top value=0.047uF
C53 "CGA3E2X7R1H473K080AA" 0603 48.5,106.25 r180 top value=0.047uF
C54 "GRM155R71H331KA01D" 0402 49,114.25 r90 top value=330pF
C55 "CGA3E2X7R1H683K080AA" 0603 43.25,107.75 r180 top value=0.068uF
C56 "C0603C331K5RACTU" 0603 92.75,94 r270 top value=330pF
C57 "C0603C331K5RACTU" 0603 102,90.5 r90 top value=330pF
C58 "CGA3E2X7R1H473K080AA" 0603 45.75,112.5 r180 top value=0.047uF
C59 "GCJ188R71E104KA12D" FP-GCJ188R71E104KA12D_0603-MFG 125.5,166 r0 top value=100nF
C60 "GCJ32DC72A475KE01L" FP-GCJ32DC72A475KE01L_1210-MFG 119,166.75 r270 top value=4.7µF
C61 "GCJ32DC72A475KE01L" FP-GCJ32DC72A475KE01L_1210-MFG 115.75,166.75 r270 top value=4.7µF
C62 "EMK316BB7226ML-T" FP-EMK316BB7226ML-T_1206-MFG 140.25,165 r90 top value=22µF
C63 "EMK316BB7226ML-T" FP-EMK316BB7226ML-T_1206-MFG 142.5,165 r90 top value=22µF
C64 "HMK107B7104KAHT" 0603 121.75,166.7 r90 top value=0.1uF
C65 "HMK107B7104KAHT" 0603 128.25,167.25 r90 top value=0.1uF
C66 "CGA3E1X7R1V105K080AE" 0603 124.25,173 r90 top value=1uF
C67 "EEV-FK2A470Q" SM_RADIAL_H13 97.5,157.5 r180 top value=47uF
C68 "C0402C100K5RAC7867" FP-C0402C100K5RAC7867_0402-MFG 135,172.5 r180 top value=10pF
C69 "GRM21BR61E226ME44L" 0805_HV 135,146.75 r180 top locked value=22uF
C70 "GRM21BZ71E106KE15L" 0805_HV 131.75,145.25 r90 top value=10uF
C71 "GRM155R71H682KA88D" 0402 134.25,140 r270 top value=6800pF
C72 "CGA3E2X7R2A223K080AA" 0603 207.25,20 r180 top value=0.022uF
C73 "GCM155R71H104KE02D" 0402 211,31 r180 top value=0.1uF
C74 "C0603X102K5RACTU" 0603 211,32.5 r180 top value=1000pF
C75 "GCM155R71H104KE02D" 0402 216.25,19.25 r270 top value=0.1uF
C76 "C0603X102K5RACTU" 0603 214.5,19.25 r270 top value=1000pF
C77 "C1608X7R1H474K080AC" 0603 207.5,29.25 r180 top value=0.47uF
C78 "CGA3E2X7R2A223K080AA" 0603 222.75,20 r0 top value=0.022uF
C79 "CGA3E2X7R2A102K080AA" 0603 100.5,23.25 r270 top value=1000pF
C80 "C1608X7R1H474K080AC" 0603 227.75,33.5 r270 top value=0.47uF
C81 "CGA3E2X7R2A223K080AA" 0603 233.75,38.125 r90 top value=0.022uF
C82 "GCM155R71H104KE02D" 0402 224.75,38.25 r270 top value=0.1uF
C83 "C0603X102K5RACTU" 0603 223,38 r270 top value=1000pF
C84 "CGA3E2X7R2A223K080AA" 0603 233.75,41.875 r270 top value=0.022uF
C85 "CGA3E2X7R2A102K080AA" 0603 100.5,19.75 r270 top value=1000pF
C86 "CGA3E2X7R2A223K080AA" 0603 199.25,21.25 r0 top value=0.022uF
C87 "GCJ188R71H224KA01D" 0603 190.875,24 r270 top value=0.22uF
C88 "06035C104KAZ2A" 0603 189.125,24 r270 top value=0.1uF
C89 "CGA3E2X7R2A223K080AA" 0603 191.75,21.25 r180 top value=0.022uF
C90 "CGA3E2X7R2A223K080AA" 0603 188.25,21.25 r0 top value=0.022uF
C91 "CGA3E2X7R2A223K080AA" 0603 180.75,21.25 r180 top value=0.022uF
C92 "06035C104KAZ2A" 0603 105.75,26.75 r90 top value=0.1uF
C93 "C0603C103J5RACTU" 0603 208,94.25 r0 top value=0.01uF
C94 "06035C104K4Z4A" 0603L 215,81.5 r90 top value=0.1uF
C95 "EEEFP1H101AP" Panasonic_SMT_800x1020 189.75,86.25 r90 top value=100uF
C96 "GRM188R61H225KE11D" 0603 203.75,82.75 r180 top value=2.2uF
C97 "CL10B562KB8NNNC" FP-CL10B562KB8NNNC_0603-IPC_C 193.75,115.5 r270 top value=5.6nF
C98 "CGA3E3X7R1H224K080AB" 0603 210.75,79.25 r270 top value=0.22uF
C99 "06035C104K4Z4A" 0603L 208.5,78.5 r0 top value=0.1uF
C100 "06035C104K4Z4A" 0603L 213,89.5 r270 top value=0.1uF
C101 "C0603C332K5RACTU" 0603 208,92.5 r180 top value=3300pF
C102 "06035C104KAZ2A" 0603 203.75,92 r180 top locked value=0.1uF
C103 "12061C223JAT2A" 1206 39.5,13.75 r180 top value=0.022uF
C104 "12061C223JAT2A" 1206 48,13.75 r0 top value=0.022uF
C105 "885012105001" WCAP-CSGP_0402_L1W0.5H0.5 46.25,22.75 r90 top
C106 "EEE-2AA100UP" SM_RADIAL_E 54.5,28.25 r180 top locked value=10uF
C107 "C3216X7R2A104K160AA" 1206_180 49.75,21.25 r90 top value=0.1uF
C108 "GCM188R72A472KA37D" 0603 92.75,30.25 r270 top value=4700pF
C109 "GRM319R72A104KA01D" 1206 25.75,18.75 r90 top value=0.1uF
C110 "C3216X7R2A224K115AA" 1206 28.5,18.75 r90 top value=0.22uF
C111 "12061C223JAT2A" 1206 16.5,13.25 r180 top value=0.022uF
C112 "GCM188R71C104KA37J" 0603 100.5,15 r270 top value=0.1uF
C113 "CGA3E2X7R2A102K080AA" 0603 41.8,148.25 r0 top value=1000pF
C114 "HMK107C7224MAHTE" 0603 51.25,137.25 r180 top value=0.22uF
C115 "KCM55WR72A156MH01K" KCM55W 132.5,179 r270 top value=15uF
C116 "HMK107C7224MAHTE" 0603 34.75,147.75 r0 top value=0.22uF
C117 "KCM55WR72A156MH01K" KCM55W 27.5,167.25 r270 top value=15uF
C118 "HMK107B7104KAHT" 0603 122,180 r270 top value=0.1uF
C119 "HMK107B7104KAHT" 0603 41.75,144.75 r0 top value=0.1uF
C120 "CGA3E2X7R2A103K080AA" 0603 41.75,146.5 r0 top locked value=0.01uF
C121 "CGA3E2X7R2A102K080AA" 0603 49.55,145.25 r0 top value=1000pF
C122 "HMK107C7224MAHTE" 0603 60,141.3 r270 top value=0.22uF
C123 "CGA3E2X7R2A103K080AA" 0603 37.25,148.55 r90 top value=0.01uF
C124 "HMK107B7104KAHT" 0603 45.2,146 r0 top value=0.1uF
C125 "CGA4J2X7R2A104K125AA" 0805_HV 47.5,139.75 r0 top value=0.1uF
C126 "CL10B105KB9VPJC" FP-CL10B105KB9VPJC_0603-MFG 44.25,139.46 r90 top value=1µF
C127 "GRM155R71H331KA01D" 0402 34.4,139.25 r180 top value=330pF
C128 "GCM188R71C104KA37J" 0603 36.75,123.25 r90 top value=0.1uF
C129 "GCJ188R71E104KA12D" FP-GCJ188R71E104KA12D_0603-MFG 43.25,136.5 r90 top value=100nF
C130 "C0603C331K5RACTU" 0603 100.25,81 r270 top value=330pF
C131 "CGA3E2X7R1H473K080AA" 0603 43,133.55 r270 top value=0.047uF
C132 "C0603C331K5RACTU" 0603 100.25,76 r270 top value=330pF
C133 "CGA3E2X7R1H473K080AA" 0603 35,137.5 r180 top value=0.047uF
C134 "GRM188R71E823KA01D" 0603 179.5,54 r90 top value=0.082uF
C135 "AFK227M63H32T-F" AFK_1250x1350 212.5,67.5 r90 top value=220uF
C136 "CGA3E2X7R1H104K080AA" 0603 225.75,66.75 r90 top value=0.1uF
C137 "C0603C223K5RACTU" 0603 180,66.25 r0 top value=0.022uF
C138 "C0603C223K5RACTU" 0603 176.625,80.25 r90 top value=0.022uF
C139 "HMK107B7104KAHT" 0603 182.625,67.375 r90 top value=0.1uF
C140 "06035C104KAZ2A" 0603 201.25,51.25 r0 top value=0.1uF
C141 "06035C104KAZ2A" 0603 183.75,59.5 r270 top value=0.1uF
C142 "06035C104KAZ2A" 0603 171.25,58.5 r180 top value=0.1uF
C143 "CGA3E2X7R2A102K080AA" 0603 163.5,131.45 r90 top value=1000pF
C144 "HMK107C7224MAHTE" 0603 185.25,121.25 r180 top value=0.22uF
C145 "KCM55WR72A156MH01K" KCM55W 117.5,179 r270 top value=15uF
C146 "HMK107B7104KAHT" 0603 128,180 r270 top value=0.1uF
C147 "HMK107C7224MAHTE" 0603 169.5,128.5 r270 top value=0.22uF
C148 "KCM55WR72A156MH01K" KCM55W 222.5,167.25 r270 top value=15uF
C149 "CGA3E2X7R2A102K080AA" 0603 177.5,129.75 r180 top value=1000pF
C150 "HMK107B7104KAHT" 0603 173.75,131.5 r0 top value=0.1uF
C151 "CGA3E2X7R2A103K080AA" 0603 173.75,129.75 r0 top value=0.01uF
C152 "HMK107C7224MAHTE" 0603 187.5,124.75 r270 top value=0.22uF
C153 "CGA3E2X7R2A103K080AA" 0603 166.75,129.55 r90 top value=0.01uF
C154 "HMK107B7104KAHT" 0603 171.25,130.75 r90 top value=0.1uF
C155 "CGA4J2X7R2A104K125AA" 0805_HV 179.25,125.25 r0 top value=0.1uF
C156 "CL10B105KB9VPJC" FP-CL10B105KB9VPJC_0603-MFG 176.25,124.71 r90 top value=1µF
C157 "GRM155R71H331KA01D" 0402 165.75,121.15 r270 top value=330pF
C158 "GCJ188R71E104KA12D" FP-GCJ188R71E104KA12D_0603-MFG 176.25,121 r90 top value=100nF
C159 "C0603C331K5RACTU" 0603 91,84.25 r270 top value=330pF
C160 "CGA3E2X7R1H473K080AA" 0603 177.05,119 r0 top value=0.047uF
C161 "C0603C331K5RACTU" 0603 100.25,86 r270 top value=330pF
C162 "CGA3E2X7R1H473K080AA" 0603 169,120.5 r180 top value=0.047uF
C163 "AGC0603X7R250-105KXP" FP-AGC0603X7R250-105KXP_0603-MFG 62,66 r180 top value=1µF
C164 "C1608X5R1E106M080AC" 0603 62.25,68 r0 top value=10uF
C165 "GCM188R72A332KA37D" 0603 42.5,67.5 r0 top value=3300pF
C166 "GCM188R72A472KA37D" 0603 30,78 r270 top value=4700pF
C167 "RC0603FR-07200RL" 0603 59.5,70 r90 top value=10uF
C168 "CGA6P1X7R1N106M250AC" 1210_280 30,86 r90 top value=10uF
C169 "GCM188R72A332KA37D" 0603 30,73 r270 top value=3300pF
C170 "GCM188R72A472KA37D" 0603 28.25,73 r90 top value=4700pF
C171 "GRM188D72A105KE01D" FP-GRM188D72A105KE01D_0603-MFG 58.25,66.5 r90 top value=1µF
C172 "GRM188D72A105KE01D" FP-GRM188D72A105KE01D_0603-MFG 56,66.5 r90 top value=1µF
C173 "CL10B105KA8VPJC" FP-CL10B105KA8VPJC_0603-MFG 52.125,66.75 r90 top value=1µF
C174 "CGA6P1X7R1N106M250AC" 1210_280 30,68.5 r90 top value=10uF
C175 "GCM188R72A332KA37D" 0603 42.5,60 r0 top value=3300pF
C176 "GCM188R72A472KA37D" 0603 30,60.5 r270 top value=4700pF
C177 "GCM188R72A332KA37D" 0603 30,55.5 r270 top value=3300pF
C178 "GCM188R72A472KA37D" 0603 28.25,55.5 r90 top value=4700pF
C179 "CL10B105KA8VPJC" FP-CL10B105KA8VPJC_0603-MFG 52.5,58.5 r180 top value=1µF
C180 "CGA6P1X7R1N106M250AC" 1210_280 30,51 r90 top value=10uF
C181 "CL10B105KA8VPJC" FP-CL10B105KA8VPJC_0603-MFG 52.5,56 r180 top value=1µF
C182 "GCM188R72A332KA37D" 0603 42.5,52.25 r0 top value=3300pF
C183 "GCM188R72A472KA37D" 0603 30,43 r270 top value=4700pF
C184 "GCM188R72A332KA37D" 0603 30,38 r270 top value=3300pF
C185 "GCM188R72A472KA37D" 0603 28.25,38 r90 top value=4700pF
C186 "C0603C471K5RACTU" 0603 92.75,89.75 r270 top value=470pF
C187 "C0603C471K5RACTU" 0603 92.75,77.125 r270 top value=470pF
C188 "C0603C471K5RACTU" 0603 102,84.5 r90 top value=470pF
C189 "CL10B104KA8VPJC" FP-CL10B104KA8VPJC_0603-MFG 66,63.25 r180 top value=100nF
C190 "CGA3E2X7R1H102K080AA" FP-CGA3E2X7R1H102K080AA_0603-MFG 47.75,50.75 r90 top value=1nF
C191 "CGA3E2X7R1H102K080AA" FP-CGA3E2X7R1H102K080AA_0603-MFG 54.75,50.75 r90 top value=1nF
C192 "CGA3E2X7R1H102K080AA" FP-CGA3E2X7R1H102K080AA_0603-MFG 61.75,50.75 r90 top value=1nF
C193 "CGA3E2X7R1H102K080AA" FP-CGA3E2X7R1H102K080AA_0603-MFG 56.25,53.75 r180 top value=1nF
C194 "CGA3E2X7R1H102K080AA" FP-CGA3E2X7R1H102K080AA_0603-MFG 58.75,53.75 r180 top value=1nF
C195 "CGA3E2X7R1H102K080AA" FP-CGA3E2X7R1H102K080AA_0603-MFG 61.25,53.75 r180 top value=1nF
C196 "CGA3E2X7R1H102K080AA" FP-CGA3E2X7R1H102K080AA_0603-MFG 53,50.75 r90 top value=1nF
C197 "CGA3E2X7R1H102K080AA" FP-CGA3E2X7R1H102K080AA_0603-MFG 60,50.75 r90 top value=1nF
C198 "CGA3E2X7R1H102K080AA" FP-CGA3E2X7R1H102K080AA_0603-MFG 67,50.75 r90 top value=1nF
C199 "GCM188R71C104KA37J" 0603 116,95.95 r90 top value=0.1uF
D1 "LTST-C191KGKT" LTST-C191_Green 153.5,7.5 r270 top value=Green
D2 "LTST-C191KGKT" LTST-C191_Green 176.5,7.5 r270 top value=Green
D3 "150060SS75000" WL-SMCW_RED 158.5,36.75 r180 top value="Super Red"
D4 "LTST-C191KGKT" LTST-C191_Green 82.5,8 r270 top value=Green
D5 "LTST-C191KGKT" LTST-C191_Green 57.5,8 r270 top value=Green
D6 "SS2H10-E3/5BT" SMB 21.25,91.25 r270 top value=100V
D7 "LTST-C191KGKT" LTST-C191_Green 17.5,90.75 r270 top value=Green
D8 "1N4148W-TP" SOD-123 55.375,99.5 r0 top value=100V
D9 "150060SS75000" WL-SMCW_RED 42.5,119 r90 top value="Super Red"
D10 "ES3G-E3/57T" SMC 149.75,163.75 r90 top value=400V
D11 "LTST-C191KGKT" LTST-C191_Green 145,162.5 r270 top value=Green
D12 "ER5JTR" SMC 133.25,151.25 r0 top locked value=600V
D13 "LTST-C191KGKT" LTST-C191_Green 144.375,146.875 r180 top value=Green
D14 "150060SS75000" WL-SMCW_RED 230,24 r90 top value="Super Red"
D15 "LTST-C191KGKT" LTST-C191_Green 203.75,5 r270 top value=Green
D16 "LTST-C191KGKT" LTST-C191_Green 226.25,5 r270 top value=Green
D17 "LTST-C191KGKT" LTST-C191_Green 235.5,32.5 r270 top value=Green
D18 "LTST-C191KGKT" LTST-C191_Green 235.5,47.5 r90 top value=Green
D19 "150060SS75000" WL-SMCW_RED 190.75,38.75 r90 top value="Super Red"
D20 "LTST-C191KGKT" LTST-C191_Green 200,18.25 r90 top value=Green
D21 "LTST-C191KGKT" LTST-C191_Green 191,18.25 r90 top value=Green
D22 "LTST-C191KGKT" LTST-C191_Green 189,18.25 r90 top value=Green
D23 "LTST-C191KGKT" LTST-C191_Green 180,18.25 r90 top value=Green
D24 "CD1408-FU1400" Diode_1408 233,91 r0 top value=400V
D25 "SMBJ13A-13-F" SMB 232.75,112.5 r180 top value=13V
D26 "SMBJ13A-13-F" SMB 224.96,112.5 r0 top value=13V
D27 "LTST-C191KGKT" LTST-C191_Green 180,87.5 r270 top value=Green
D28 "150060SS75000" WL-SMCW_RED 23.5,29.25 r90 top value="Super Red"
D29 "LTST-C191KGKT" LTST-C191_Green 36.25,4.25 r0 top value=Green
D30 "LTST-C191KGKT" LTST-C191_Green 51.25,4.25 r180 top value=Green
D31 "LTST-C191KGKT" LTST-C191_Green 13.75,5.75 r270 top value=Green
D32 "CD1408-FU1400" Diode_1408 125,189.5 r270 top value=400V
D33 "CD1408-FU1400" Diode_1408 90,192.5 r180 top value=400V
D34 "SMAJ51CA" SMA_Bi 32.25,167.25 r90 top value=51V
D35 "LTST-C191KGKT" LTST-C191_Green 125,177 r270 top value=Green
D36 "1N4148W-TP" SOD-123 55,144.75 r90 top value=100V
D37 "150060SS75000" WL-SMCW_RED 31.2,136.75 r180 top value="Super Red"
D38 "SS2H10-E3/5BT" SMB 222.5,67.5 r90 top value=100V
D39 "SMAJ20CA" SMA_Bi 184,79.25 r90 top value=20V
D40 "LTST-C191KGKT" LTST-C191_Green 244.5,50 r90 top value=Green
D41 "150060SS75000" WL-SMCW_RED 170.95,70.25 r0 top value="Super Red"
D42 "150060SS75000" WL-SMCW_RED 174.25,70.25 r0 top value="Super Red"
D43 "CD1408-FU1400" Diode_1408 160,192.5 r0 top value=400V
D44 "SMAJ51CA" SMA_Bi 217.5,167.25 r90 top value=51V
D45 "1N4148W-TP" SOD-123 182.5,129.75 r90 top value=100V
D46 "150060SS75000" WL-SMCW_RED 169.3,117 r0 top value="Super Red"
D47 "LTST-C191KGKT" LTST-C191_Green 33,72 r180 top value=Green
D48 "LTST-C191KGKT" LTST-C191_Green 33,54.5 r180 top value=Green
D49 "LTST-C191KGKT" LTST-C191_Green 33,37 r180 top value=Green
D50 "150060SS75000" WL-SMCW_RED 63.2,69.75 r180 top value="Super Red"
D51 "1N4148W-TP" SOD-123 55,139.75 r90 top value=100V
D52 "1N4148W-TP" SOD-123 185,125 r270 top value=100V
D53 "1N4148W-TP" SOD-123 54.388,155.75 r0 top value=100V
D54 "1N4148W-TP" SOD-123 163,140.137 r90 top value=100V
D55 "STPS1150A" SMA 294.75,33.25 r90 top value=150V
D56 "STPS1150A" SMA 302.25,33 r90 top value=150V
D57 "STPS1150A" SMA 308.25,33 r90 top value=150V
D58 "STPS1150A" SMA 314.75,33.25 r90 top value=150V
D59 "SS2H10-E3/5BT" SMB 295,20.79 r90 top value=100V
D60 "SS2H10-E3/5BT" SMB 321.25,26.75 r90 top value=100V
D61 "SS2H10-E3/5BT" SMB 303.75,20.25 r90 top value=100V
D62 "SS2H10-E3/5BT" SMB 289.5,19.71 r90 top value=100V
D63 "SS2H10-E3/5BT" SMB 316.5,11.75 r90 top value=100V
D64 "SS2H10-E3/5BT" SMB 277.5,30.71 r270 top value=100V
D65 "SS2H10-E3/5BT" SMB 296.75,5.71 r90 top value=100V
H1 "NY PMS 440 0025 PH" "NY PMS 440 0025 PH" 5,195 r0 top
H2 "NY PMS 440 0025 PH" "NY PMS 440 0025 PH" 245,195 r0 top
H3 "NY PMS 440 0025 PH" "NY PMS 440 0025 PH" 5,5 r0 top
H4 "NY PMS 440 0025 PH" "NY PMS 440 0025 PH" 245,5 r0 top
H5 "NY PMS 440 0025 PH" "NY PMS 440 0025 PH" 118,54 r0 top locked
H6 "1902C" Keystone_1902C 5,195 r180 bottom
H7 "1902C" Keystone_1902C 245,195 r180 bottom
H8 "1902C" Keystone_1902C 5,5 r180 bottom
H9 "1902C" Keystone_1902C 245,5 r180 bottom
H10 "1902C" Keystone_1902C 118,54 r180 bottom
J1 "Cobra_EN" TSW-103-07-G-S 100,168.75 r180 top
J2 "5V_Buck_EN" TSW-103-07-G-S 104.25,143.46 r270 top
J3 "482H85_DIAG_EN" TSW-103-07-G-S 7.5,18.25 r180 top
J4 "1HTC30_DIAG_EN" TSW-103-07-G-S 7.5,22.75 r180 top
J5 "DRV8363" Phoenix_1904150 10,57.5 r270 top locked
J6 "TPS482H85" PhoenixContact_1715721 43.75,6.25 r0 top
J7 "TPS1HTC30" PhoenixContact_1715721 21.25,6.25 r0 top locked
J8 "DRV8245" Phoenix_1902547 165,9.25 r0 top locked
J9 "DRV8263" Phoenix_1902547 70,9.25 r0 top locked
J10 "TPS2HCS05" Phoenix_1902547 215,9.25 r0 top locked
J11 "TPS2HCS10" PhoenixContact_1715721 243.75,40 r90 top locked
J12 "TPS4HC120" Phoenix_1715048 190,6.5 r0 top locked
J13 "SSQ-110-03-T-D" BoosterPack_40pin_J1J3 96.52,85.725 r180 bottom locked
J14 "SSQ-110-03-T-D" BoosterPack_40pin_J2J4 139.7,85.725 r180 bottom locked
J15 "SSQ-110-03-T-D" BoosterPack_40pin_J6J8 139.7,22.225 r180 bottom locked
J16 "3.3V" Foxconn_HB3902U 96.5,142.5 r270 top
J17 "5V" Foxconn_HB3902U 100.5,142.5 r90 top
J18 "SSQ-110-03-T-D" BoosterPack_40pin_J5J7 96.52,22.225 r180 bottom locked
J19 "482H85_SEL" TSW-103-07-G-S 7.5,14 r180 top
J20 "Extra_TPLD" TSW-104-07-G-S 27.5,124.25 r270 top
L1 "7443320100" WE-HCC_1210 165,79 r270 top value=1uH
L2 "7443320100" WE-HCC_1210 80,70 r270 top value=1uH
L3 "7440650022" WE-TPC-XLH2 130.625,160 r0 top locked value=2.2uH
L4 "7447709220" WE-PD_1210 107.5,177.5 r270 top value=22uH
L5 "XGL4030-102MEC" FP-XGL4030-102MEC_SMD_IND_4MM0_4MM0-MFG 139.5,145.25 r90 top locked value=1uH
LBL1 "THT-14-423-10" Label_650x200 64.75,194 r0 top
LOGO1 "CAUTION HOT SURFACE" IEC_HotSurface_Small 144.5,185.25 r0 top
Logo2 "CE Mark" CE_Mark_5mm 119.342,181.217 r180 bottom
Logo3 "Texas Instruments" TI_Stacked_Overlay_Small 171,159.5 r0 top
Logo4 "FCC disclaimer" FCC_disclaimer 64.375,193 r180 bottom
Logo5 "WEEE logo" WEEE_Minimum 110.592,182.418 r180 bottom
Q1 "NVMTS1D2N08H" FP-NVMTS1D2N08H_DFNW8-MFG 37.5,92.5 r180 top locked
Q2 "NVMTS1D2N08H" FP-NVMTS1D2N08H_DFNW8-MFG 47.5,92.43 r180 top locked
Q3 "BUK7J1R4-40HX" FP-BUK7J1R4-40HX_LFPAK56E-MFG 218,106.5 r90 top locked
Q4 "BUK7J1R4-40HX" FP-BUK7J1R4-40HX_LFPAK56E-MFG 202,106.5 r270 top locked
Q5 "BUK7J1R4-40HX" FP-BUK7J1R4-40HX_LFPAK56E-MFG 218,98.5 r90 top locked
Q6 "BUK7J1R4-40HX" FP-BUK7J1R4-40HX_LFPAK56E-MFG 202,98.5 r270 top locked
Q7 "NVMTS1D2N08H" FP-NVMTS1D2N08H_DFNW8-MFG 73.32,177.25 r270 top
Q9 "NVMTS1D2N08H" FP-NVMTS1D2N08H_DFNW8-MFG 62.5,167.5 r180 top locked
Q10 "NVMTS1D2N08H" FP-NVMTS1D2N08H_DFNW8-MFG 60.5,182.5 r0 top locked
Q11 "NVMTS1D2N08H" FP-NVMTS1D2N08H_DFNW8-MFG 45,167.5 r180 top locked
Q12 "NVMTS1D2N08H" FP-NVMTS1D2N08H_DFNW8-MFG 43,182.5 r0 top
Q13 "BSS138W-7-F" SOT-323 31.5,149.25 r180 top value=50V
Q14 "SIR662DP-T1-GE3" PowerPAK_SO-8 200,65.5 r180 top locked value=60V
Q15 "SIR662DP-T1-GE3" PowerPAK_SO-8 200,57.5 r180 top value=60V
Q16 "MMBT3904TT1G" SOT-416 174.5,57.25 r90 top value="40 V"
Q17 "NVMTS1D2N08H" FP-NVMTS1D2N08H_DFNW8-MFG 176.18,176.25 r90 top
Q18 "NVMTS1D2N08H" FP-NVMTS1D2N08H_DFNW8-MFG 189.5,167.5 r180 top locked
Q19 "NVMTS1D2N08H" FP-NVMTS1D2N08H_DFNW8-MFG 187.5,182.5 r0 top locked
Q20 "NVMTS1D2N08H" FP-NVMTS1D2N08H_DFNW8-MFG 207,167.5 r180 top locked
Q21 "NVMTS1D2N08H" FP-NVMTS1D2N08H_DFNW8-MFG 205,182.5 r0 top locked
Q22 "BSS138W-7-F" SOT-323 161.25,135.25 r270 top value=50V
Q23 "CSD19534Q5A" DQJ0008A 25.25,81.75 r90 top value=100V
Q24 "CSD19534Q5A" DQJ0008A 23.75,74.25 r90 top value=100V
Q25 "CSD19534Q5A" DQJ0008A 25.25,64.25 r90 top value=100V
Q26 "CSD19534Q5A" DQJ0008A 23.75,56.75 r90 top value=100V
Q27 "CSD19534Q5A" DQJ0008A 25.25,46.75 r90 top value=100V
Q28 "CSD19534Q5A" DQJ0008A 23.75,39.25 r90 top locked value=100V
R1 "RC0603FR-07750RL" 0603 153.5,11.5 r90 top value=750
R2 "RC0603FR-07750RL" 0603 176.5,11.5 r90 top value=750
R3 "RC0603FR-07205RL" 0603 156,35.75 r270 top value=205
R4 "RC0603JR-0710KL" 0603 158.75,34.75 r180 top value=10k
R5 "Resistor" 0603L 102.5,29.25 r180 top value=0
R6 "RC0402JR-0710KL" FP-RC0402JR-0710KL_0402-MFG 167.5,34 r180 top value=10k
R7 "RC0201FR-0722RL" 0201 164.5,33.5 r270 top value=22.0
R8 "CRCW06031K00FKEA" 0603 158.75,33 r0 top value=1.00k
R9 "RC0201FR-0722RL" 0201 166.25,33.5 r270 top value=22.0
R10 "RC0201FR-0722RL" 0201 165.5,33.5 r270 top value=22.0
R11 "RC0201FR-0722RL" 0201 163.75,33.5 r270 top value=22.0
R12 "Resistor" 0603L 92.5,20 r0 top value=0
R13 "RC0201FR-0722RL" 0201 69.75,33.5 r270 top value=22.0
R14 "RC0603FR-071KL" 0603 90.25,21 r270 top value=1.00k
R15 "RC0603FR-072K49L" 0603 82.5,11.25 r90 top value=2.49k
R16 "RC0603FR-072K49L" 0603 57.5,11.25 r90 top value=2.49k
R17 "RC0201FR-0722RL" 0201 69,33.5 r270 top value=22.0
R18 "RC0402JR-0710KL" FP-RC0402JR-0710KL_0402-MFG 71.875,34.25 r180 top value=10k
R19 "RC0201FR-0722RL" 0201 68.25,33.5 r270 top value=22.0
R20 "RC0201FR-0722RL" 0201 70.5,33.5 r270 top value=22.0
R21 "VMP-1R00-1.0-U" FP-VMP-1R00-1.0-U_2010-MFG 58.5,83.75 r180 top value=1
R22 "CRCW06030000Z0EA" 0603 55.75,117.25 r0 top value=0
R23 "CRCW06030000Z0EA" 0603 55.75,115.25 r0 top value=0
R24 "CRCW06030000Z0EA" 0603 43.5,103.5 r180 top value=0
R25 "RC0805FR-0710RL" 0805_HV 43.5,105.5 r0 top value=10.0
R26 "WSL3921L5000FEA" FP-WSL3921L5000FEA_3921-MFG 58,91.25 r180 top locked value=500µ
R27 "ERJ-3EKF1000V" 0603 57,112.25 r90 top value=100
R28 "CRCW06030000Z0EA" 0603 61.75,108 r0 top value=0
R29 "CRCW06030000Z0EA" 0603 61.75,106 r0 top value=0
R30 "RC0603FR-072K49L" 0603 17.5,93.75 r90 top value=2.49k
R31 "RC0603FR-07200RL" 0603 58.25,108 r0 top value=200
R32 "CRCW06030000Z0EA" 0603 58.25,106 r0 top value=0
R33 "RC0603FR-072R21L" 0603 54.25,95.625 r180 top value=2.21
R34 "CGA4J2X7R2A104K125AA" 0805_HV 54.75,102 r180 top value=10.0
R35 "RNCF0603TKY10K0" 0603 53.75,119 r0 top value=10.0k
R36 "RC0603FR-07820RL" 0603 59.75,111.25 r0 top value=820
R37 "RC0603FR-07309RL" 0603 54.375,104 r0 top value=309
R38 "CRCW06030000Z0EA" 0603 54.25,97.375 r180 top value=0
R39 "RC0603FR-07205RL" 0603 42.5,122.2 r90 top value=205
R40 "TNPW060310K0BEEA" TNPW0603 45.75,116 r180 top value=10.0k
R41 "TNPW060310K0BEEA" TNPW0603 45.75,117.75 r180 top value=10.0k
R42 "CRCW06034K02FKEA" 0603 91,94 r90 top value=4.02k
R43 "RC0603FR-0712KL" 0603 43.25,109.75 r0 top value=12.0k
R44 "CRCW0603100KFKEA" 0603 45.75,114.25 r0 top value=100k
R45 "RC0603FR-0740K2L" 0603 100.25,90.5 r270 top value=40.2k
R46 "CRCW06031R54FKEA" 0603 118.25,162 r90 top value=1.54
R47 "RC0603FR-07510RL" 0603 145,165.75 r90 top value=510
R48 "ERJ-3EKF1002V" 0603 116.75,162 r90 top value=10.0k
R49 "RT0603BRD07100KL" 0603 115,162 r90 top value=100k
R50 "RT0603BRD07100KL" 0603 128.5,173 r90 top value=100k
R51 "ERJ-3EKF1002V" 0603 122.5,173 r270 top value=10.0k
R52 "RC0603FR-0797K6L" 0603 131.5,170.75 r0 top value=97.6k
R53 "RC0603FR-0797K6L" 0603 135,170.75 r180 top value=97.6k
R54 "RC0603FR-079K53L" 0603 131.5,172.5 r180 top value=9.53k
R55 "RC0603FR-079K53L" 0603 126,173 r270 top value=9.53k
R56 "ERJ-3EKF1002V" 0603 96.5,166 r0 top value=10.0k
R57 "ERJ-3EKF1002V" 0603 109.75,143.95 r90 top value=10.0k
R58 "RC0603FR-07200RL" 0603 144.25,148.75 r180 top value=200
R59 "CRCW0603118KFKEA" 0603 136.25,140 r90 top value=118k
R60 "RC0603FR-0726K1L" 0603 132.5,141.25 r90 top value=26.1k
R61 "RC0402JR-0710KL" FP-RC0402JR-0710KL_0402-MFG 138.25,142 r0 top value=10k
R62 "ERJ-3EKF1002V" 0603 109.75,140.5 r90 top value=10.0k
R63 "RC0603FR-0710RL" 0603 207.5,31 r0 top value=10.0
R64 "RC0603FR-07205RL" 0603 230,27.5 r90 top value=205
R65 "CRCW0603100RJNEA" 0603 221.25,31.25 r180 top value=100
R66 "RMCF0603FT10K0" 0603 225,29.5 r0 top value=10.0k
R67 "CRCW0603100RJNEA" 0603 221.25,26 r180 top value=100
R68 "CRCW0603100RJNEA" 0603 221.25,27.75 r180 top value=100
R69 "RC0603FR-07750RL" 0603 203.75,8.75 r90 top value=750
R70 "RC0603FR-07750RL" 0603 226.25,8.75 r90 top value=750
R71 "RMCF0603FT10K0" 0603 207.5,25.75 r180 top value=10.0k
R72 "CRCW0603100RJNEA" 0603 221.25,29.5 r180 top value=100
R73 "RC0603FR-07698RL" 0603 102.25,23.25 r90 top value=698
R74 "RMCF0603FT10K0" 0603 207.5,24 r180 top value=10.0k
R75 "RMCF0603FT10K0" 0603 207.5,27.5 r180 top value=10.0k
R76 "RC0603FR-0710RL" 0603 226,33.5 r90 top value=10.0
R77 "RC0603FR-07750RL" 0603 235.5,35.5 r90 top value=750
R78 "RC0603FR-07750RL" 0603 235.5,44.5 r270 top value=750
R79 "RMCF0603FT10K0" 0603 229.5,33.5 r270 top value=10.0k
R80 "RMCF0603FT10K0" 0603 233,33.5 r270 top value=10.0k
R81 "RMCF0603FT10K0" 0603 231.25,33.5 r270 top value=10.0k
R82 "RC0603FR-074K7L" 0603 231.25,46.25 r90 top value=4.70k
R83 "CRCW0603100RJNEA" 0603 222.5,46.25 r270 top value=100
R84 "RMCF0603FT10K0" 0603 229.5,46.25 r270 top value=10.0k
R85 "RC0603FR-07698RL" 0603 102.25,19.75 r90 top value=698
R86 "CRCW0603100RJNEA" 0603 227.75,46.25 r270 top value=100
R87 "CRCW0603100RJNEA" 0603 226,46.25 r270 top value=100
R88 "RC0402JR-0710KL" FP-RC0402JR-0710KL_0402-MFG 224.25,50 r270 top value=10k
R89 "CRCW0603100RJNEA" 0603 224.25,46.25 r270 top value=100
R90 "RMCF0603FT10K0" 0603 198.75,32.5 r0 top value=10.0k
R91 "RMCF0603FT10K0" 0603 198.75,34.25 r0 top value=10.0k
R92 "RMCF0603FT10K0" 0603 198.75,36 r0 top value=10.0k
R93 "RMCF0603FT10K0" 0603 198.75,37.75 r0 top value=10.0k
R94 "RMCF0603FT10K0" 0603 192.5,38.5 r90 top value=10.0k
R95 "RMCF0603FT10K0" 0603 194.25,38.5 r90 top value=10.0k
R96 "RMCF0603FT10K0" 0603 196,38.5 r90 top value=10.0k
R97 "CRCW06034K99FKEA" 0603 189,38.5 r90 top value=4.99k
R98 "CRCW06034K99FKEA" 0603 183.75,38.5 r90 top value=4.99k
R99 "RMCF0603FT10K0" 0603 187.25,38.5 r90 top value=10.0k
R100 "RMCF0603FT10K0" 0603 185.5,38.5 r90 top value=10.0k
R101 "RMCF0603FT10K0" 0603 101.25,26 r180 top value=10.0k
R102 "CRCW060323K2FKEA" 0603 185,33 r90 top value=23.2k
R103 "ESR03EZPJ102" 0603 104,26.75 r270 top value=1.0k
R104 "RC0603FR-07205RL" 0603 190,41.25 r180 top value=205
R105 "RC0603FR-07750RL" 0603 199.25,16 r180 top value=750
R106 "RC0603FR-07750RL" 0603 191.75,16 r0 top value=750
R107 "RC0603FR-07750RL" 0603 188.25,16 r180 top value=750
R108 "RC0603FR-07750RL" 0603 180.75,16 r0 top value=750
R109 "CSS2H-2512R-L500F" FP-CSS2H-2512R-L500F_2512-MFG 201.25,111.75 r180 top value=500µ
R110 "CSS2H-2512R-L500F" FP-CSS2H-2512R-L500F_2512-MFG 201.25,116.25 r180 top value=500µ
R111 "HoLRS2512-0.25mR-1%" FP-HoLRS2512_2512-MFG 210,102.5 r180 top value=250µ
R112 "CRCW060350R0FKEA" 0603 212,94.25 r0 top value=50
R113 "ERJ-3GEY0R00V" 0603 193.75,112.5 r90 top value=0
R114 "ERJ-3GEY0R00V" 0603 221.25,90 r90 top value=0
R115 "ERJ-3GEY0R00V" 0603 218.75,90 r90 top value=0
R116 "RC0603FR-07750RL" 0603 182.5,87.5 r270 top value=750
R117 "CRCW06030000Z0EA" 0603 203.75,84.5 r180 top locked value=0
R118 "CRCW060350R0FKEA" 0603 212,92.5 r0 top value=50
R119 "RT0603BRD0720K8L" 0603 214.5,89.5 r270 top value=20.8k
R120 "ERJ-PB3B1003V" FP-ERJ-PB3B1003V_0603-IPC_A 214.5,84.5 r90 top value=100k
R121 "RT0603BRD071K62L" 0603 216.75,89.5 r270 top value=1.62k
R122 "ERJ-PB3B1003V" FP-ERJ-PB3B1003V_0603-IPC_A 216.75,84.5 r90 top value=100k
R123 "ERJ-3EKF1002V" 0603 211.5,89.75 r90 top value=10.0k
R124 "ERJ-3EKF1002V" 0603 209.75,89.75 r90 top value=10.0k
R125 "ERJ-3EKF1002V" 0603 203.75,86.25 r180 top locked value=10.0k
R126 "RC0603FR-076K2L" 0603 100.5,11 r90 top value=6.20k
R127 "RC0603FR-0740K2L" 0603 203.75,88 r0 top locked value=40.2k
R128 "ERJ-PB3B1003V" FP-ERJ-PB3B1003V_0603-IPC_A 203.75,90 r180 top locked value=100k
R129 "RNCF0603TKY10K0" 0603 39.5,27.75 r90 top value=10.0k
R130 "RNCF0603TKY10K0" 0603 48.25,27.25 r90 top value=10.0k
R131 "RC0603FR-074K7L" 0603 41.25,27.75 r270 top value=4.70k
R132 "RC0603FR-074K7L" 0603 46.5,27.25 r270 top value=4.70k
R133 "CRCW06034K99FKEAC" 0603 90,31.25 r0 top value=4.99k
R134 "RNCF0603TKY10K0" 0603 37.75,26.95 r90 top value=10.0k
R135 "ERA3AEB102V" 0603 90,29.25 r180 top value=1.00k
R136 "RC0603FR-07205RL" 0603 22.75,31.5 r180 top value=205
R137 "RC0603FR-0726K1L" 0603 40.5,23.75 r270 top value=26.1k
R138 "RNCF0603TKY10K0" 0603 44.75,27.75 r90 top value=10.0k
R139 "RC0603FR-072K49L" 0603 36.25,6.25 r0 top value=2.49k
R140 "RC0603FR-072K49L" 0603 51.25,6.25 r180 top value=2.49k
R141 "RNCF0603TKY10K0" 0603 43,28 r270 top value=10.0k
R142 "RNCF0603TKY10K0" 0603 26.5,26 r0 top value=10.0k
R143 "CRCW06034K99FKEAC" 0603 26.5,28 r180 top value=4.99k
R144 "CRCW06034K99FKEAC" 0603 17.75,28.75 r270 top value=4.99k
R145 "ERJ-3GEY0R00V" 0603 17.5,23.25 r90 top value=0
R146 "ERJ-3EKF1002V" 0603 21.75,28.75 r90 top value=10.0k
R147 "CRCW06034K99FKEAC" 0603 19.5,28.75 r270 top value=4.99k
R148 "CRCW06034K99FKEAC" 0603 102.25,15 r270 top value=4.99k
R149 "RNCF0603TKY10K0" 0603 27,29.75 r0 top value=10.0k
R150 "RC0603FR-072K49L" 0603 13.75,9.5 r90 top value=2.49k
R151 "ERJ-3EKF1001V" 0603 16,28.75 r270 top value=1.00k
R152 "RNCF0603TKY10K0" 0603 27,31.5 r180 top value=10.0k
R153 "VMP-1R00-1.0-U" FP-VMP-1R00-1.0-U_2010-MFG 74.5,187.75 r270 top value=1
R154 "CRCW06030000Z0EA" 0603 42.75,151.25 r90 top value=0
R155 "CRCW06030000Z0EA" 0603 40.75,151.25 r90 top value=0
R156 "RC0603FR-073K16L" 0603 133.5,13.3 r90 top value=3.16k
R157 "CRCW06030000Z0EA" 0603 47.25,135.25 r0 top value=0
R158 "RC0805FR-0710RL" 0805_HV 47.5,137.25 r180 top value=10.0
R159 "CSS2H-2512R-L500F" FP-CSS2H-2512R-L500F_2512-MFG 55.75,170.9 r270 top value=500µ
R160 "CSS2H-2512R-L500F" FP-CSS2H-2512R-L500F_2512-MFG 51.5,170.9 r270 top value=500µ
R161 "RC0603FR-072K49L" 0603 125,180 r90 top value=2.49k
R162 "HoLRS2512-0.25mR-1%" FP-HoLRS2512_2512-MFG 51.5,187.75 r270 top value=250µ
R163 "CRCW06030000Z0EA" 0603 50.75,151.25 r90 top value=0
R164 "CRCW06030000Z0EA" 0603 48.75,151.25 r90 top value=0
R165 "CRCW06030000Z0EA" 0603 45,151.25 r90 top value=0
R166 "ERJ-3EKF1000V" 0603 39,147.5 r90 top value=100
R167 "RC0603FR-07200RL" 0603 50.75,147.75 r90 top value=200
R168 "RC0603FR-07200RL" 0603 48.75,147.75 r90 top value=200
R169 "RC0603FR-072R21L" 0603 60,148.75 r90 top value=2.21
R170 "RC0603FR-072R21L" 0603 55,148.75 r90 top value=2.21
R171 "RC0603FR-072R21L" 0603 62.5,148.7 r90 top value=2.21
R172 "RC0603FR-07300KL" 0603 38.25,144.75 r0 top value=300k
R173 "RC0603FR-072R21L" 0603 57.5,148.75 r90 top value=2.21
R174 "RC0805FR-0710RL" 0805_HV 60,145 r90 top value=10.0
R175 "RC0603FR-0775KL" 0603 33.3,151.5 r0 top value=75.0k
R176 "RC0603FR-071KL" 0603 32.45,144 r0 top value=1.00k
R177 "RC0603FR-07698RL" 0603 46.75,151.25 r90 top value=698
R178 "RC0603FR-071KL" 0603 34.5,145.75 r180 top value=1.00k
R179 "CRCW06030000Z0EA" 0603 47.75,143 r180 top value=0
R180 "RC0603FR-07309RL" 0603 51.95,142.5 r0 top value=309
R181 "RC0603FR-071KL" 0603 134.3,10.75 r180 top value=1.00k
R182 "CRCW06030000Z0EA" 0603 57.5,145.2 r270 top value=0
R183 "RC0603FR-07205RL" 0603 29.7,135 r180 top value=205
R184 "TNPW060310K0BEEA" TNPW0603 31.25,138.5 r180 top value=10.0k
R185 "RC0603FR-071KL" 0603 32.25,134.2 r270 top value=1.00k
R186 "TNPW060310K0BEEA" TNPW0603 31.25,140.25 r180 top value=10.0k
R187 "RC0603FR-071KL" 0603 32.45,142 r0 top value=1.00k
R188 "RC0603FR-072K2L" 0603 102,81 r90 top value=2.20k
R189 "RC0603FR-0712K1L" 0603 41.25,135 r90 top value=12.1k
R190 "CRCW0603100KFKEA" 0603 35,135.75 r0 top value=100k
R191 "RC0603FR-0710RL" 0603 52,140.5 r180 top value=10.0
R192 "ALN2512F50R0E-1" FP-ALN2512F50R0E-1_2512-MFG 192.5,65.5 r0 top value=50
R193 "RC0603FR-072R21L" 0603 181.25,57.5 r270 top value=2.21
R194 "RC0603FR-07300RL" 0603 179.5,57.5 r270 top value=300
R195 "ULRG32512R001FLFSLT" FP-ULRG32512R001FLFSLT_2512-MFG 192.5,57.5 r0 top value=1m
R196 "CRCW06030000Z0EA" 0603 187.625,63.875 r270 top value=0
R197 "CRCW06030000Z0EA" 0603 185.125,63.125 r0 top value=0
R198 "RC0603FR-07100RL" 0603 180,80.2 r270 top value=100
R199 "RC0603FR-07750RL" 0603 242.5,50 r90 top value=750
R200 "RC0603FR-07402KL" 0603 175.75,68 r180 top value=402k
R201 "CRCW060350R0FKEA" 0603 185.125,64.75 r180 top value=50
R202 "RC0603FR-072R21L" 0603 197.5,53 r0 top value=2.21
R203 "RC0603FR-0782K5L" 0603 175.75,66.25 r0 top value=82.5k
R204 "CRCW06030000Z0EA" 0603 197.5,51.25 r180 top value=0
R205 "RC0603FR-0710RL" 0603 193.75,53 r180 top value=10.0
R206 "CRCW06030000Z0EA" 0603 193.75,51.25 r180 top value=0
R207 "ERJ-PB3B1003V" FP-ERJ-PB3B1003V_0603-IPC_A 171.25,56.5 r180 top value=100k
R208 "ERJ-3EKF1002V" 0603 170,67 r270 top value=10.0k
R209 "CRCW06030000Z0EA" 0603 176.5,57.25 r90 top value=0
R210 "ERJ-3EKF1002V" 0603 172,66.75 r270 top value=10.0k
R211 "RC0603FR-0714K7L" 0603 104.25,18.25 r270 top value=14.7k
R212 "RC0603FR-0747K5L" 0603 171.25,60.25 r0 top value=47.5k
R213 "RC0603FR-071K33L" 0603 184.5,67.375 r270 top value=1.33k
R214 "RC0603FR-07205RL" 0603 170.95,72 r180 top value=205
